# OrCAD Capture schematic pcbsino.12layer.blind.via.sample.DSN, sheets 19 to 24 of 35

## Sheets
19 Pg05: Power Supply 1: size C
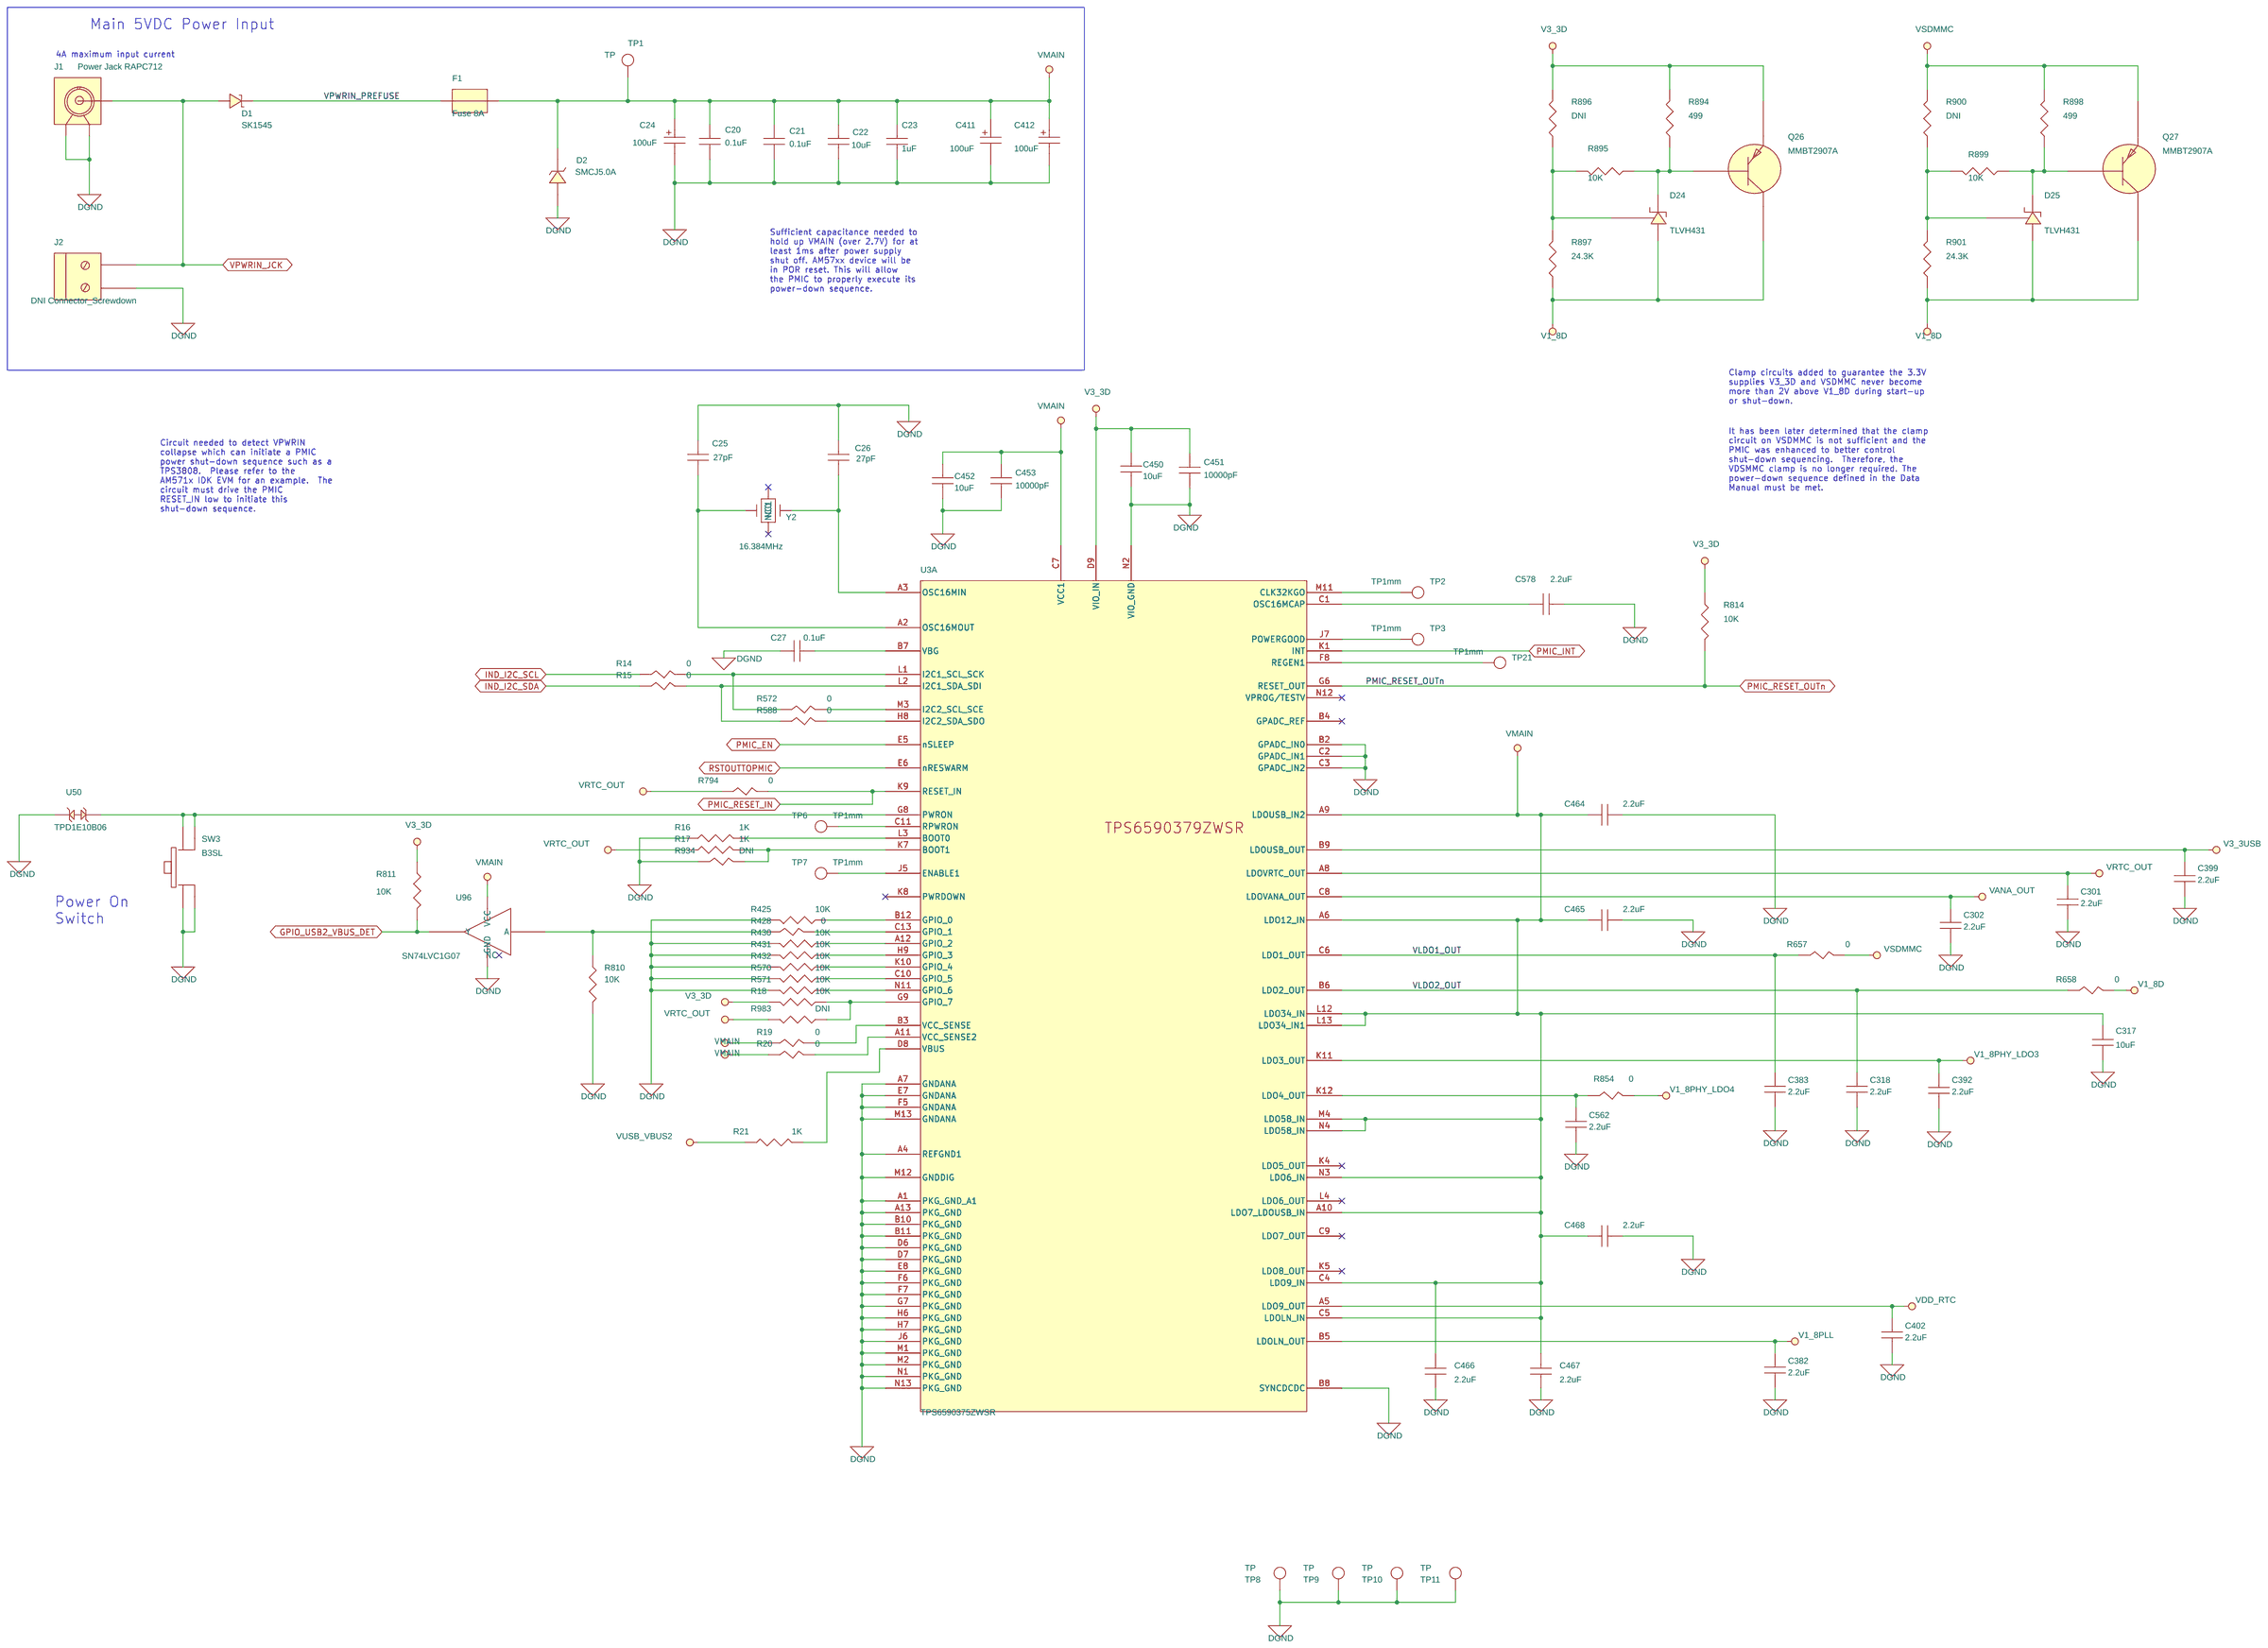
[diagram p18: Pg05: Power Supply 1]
20 Pg09: DDR3 Memory 2: size C
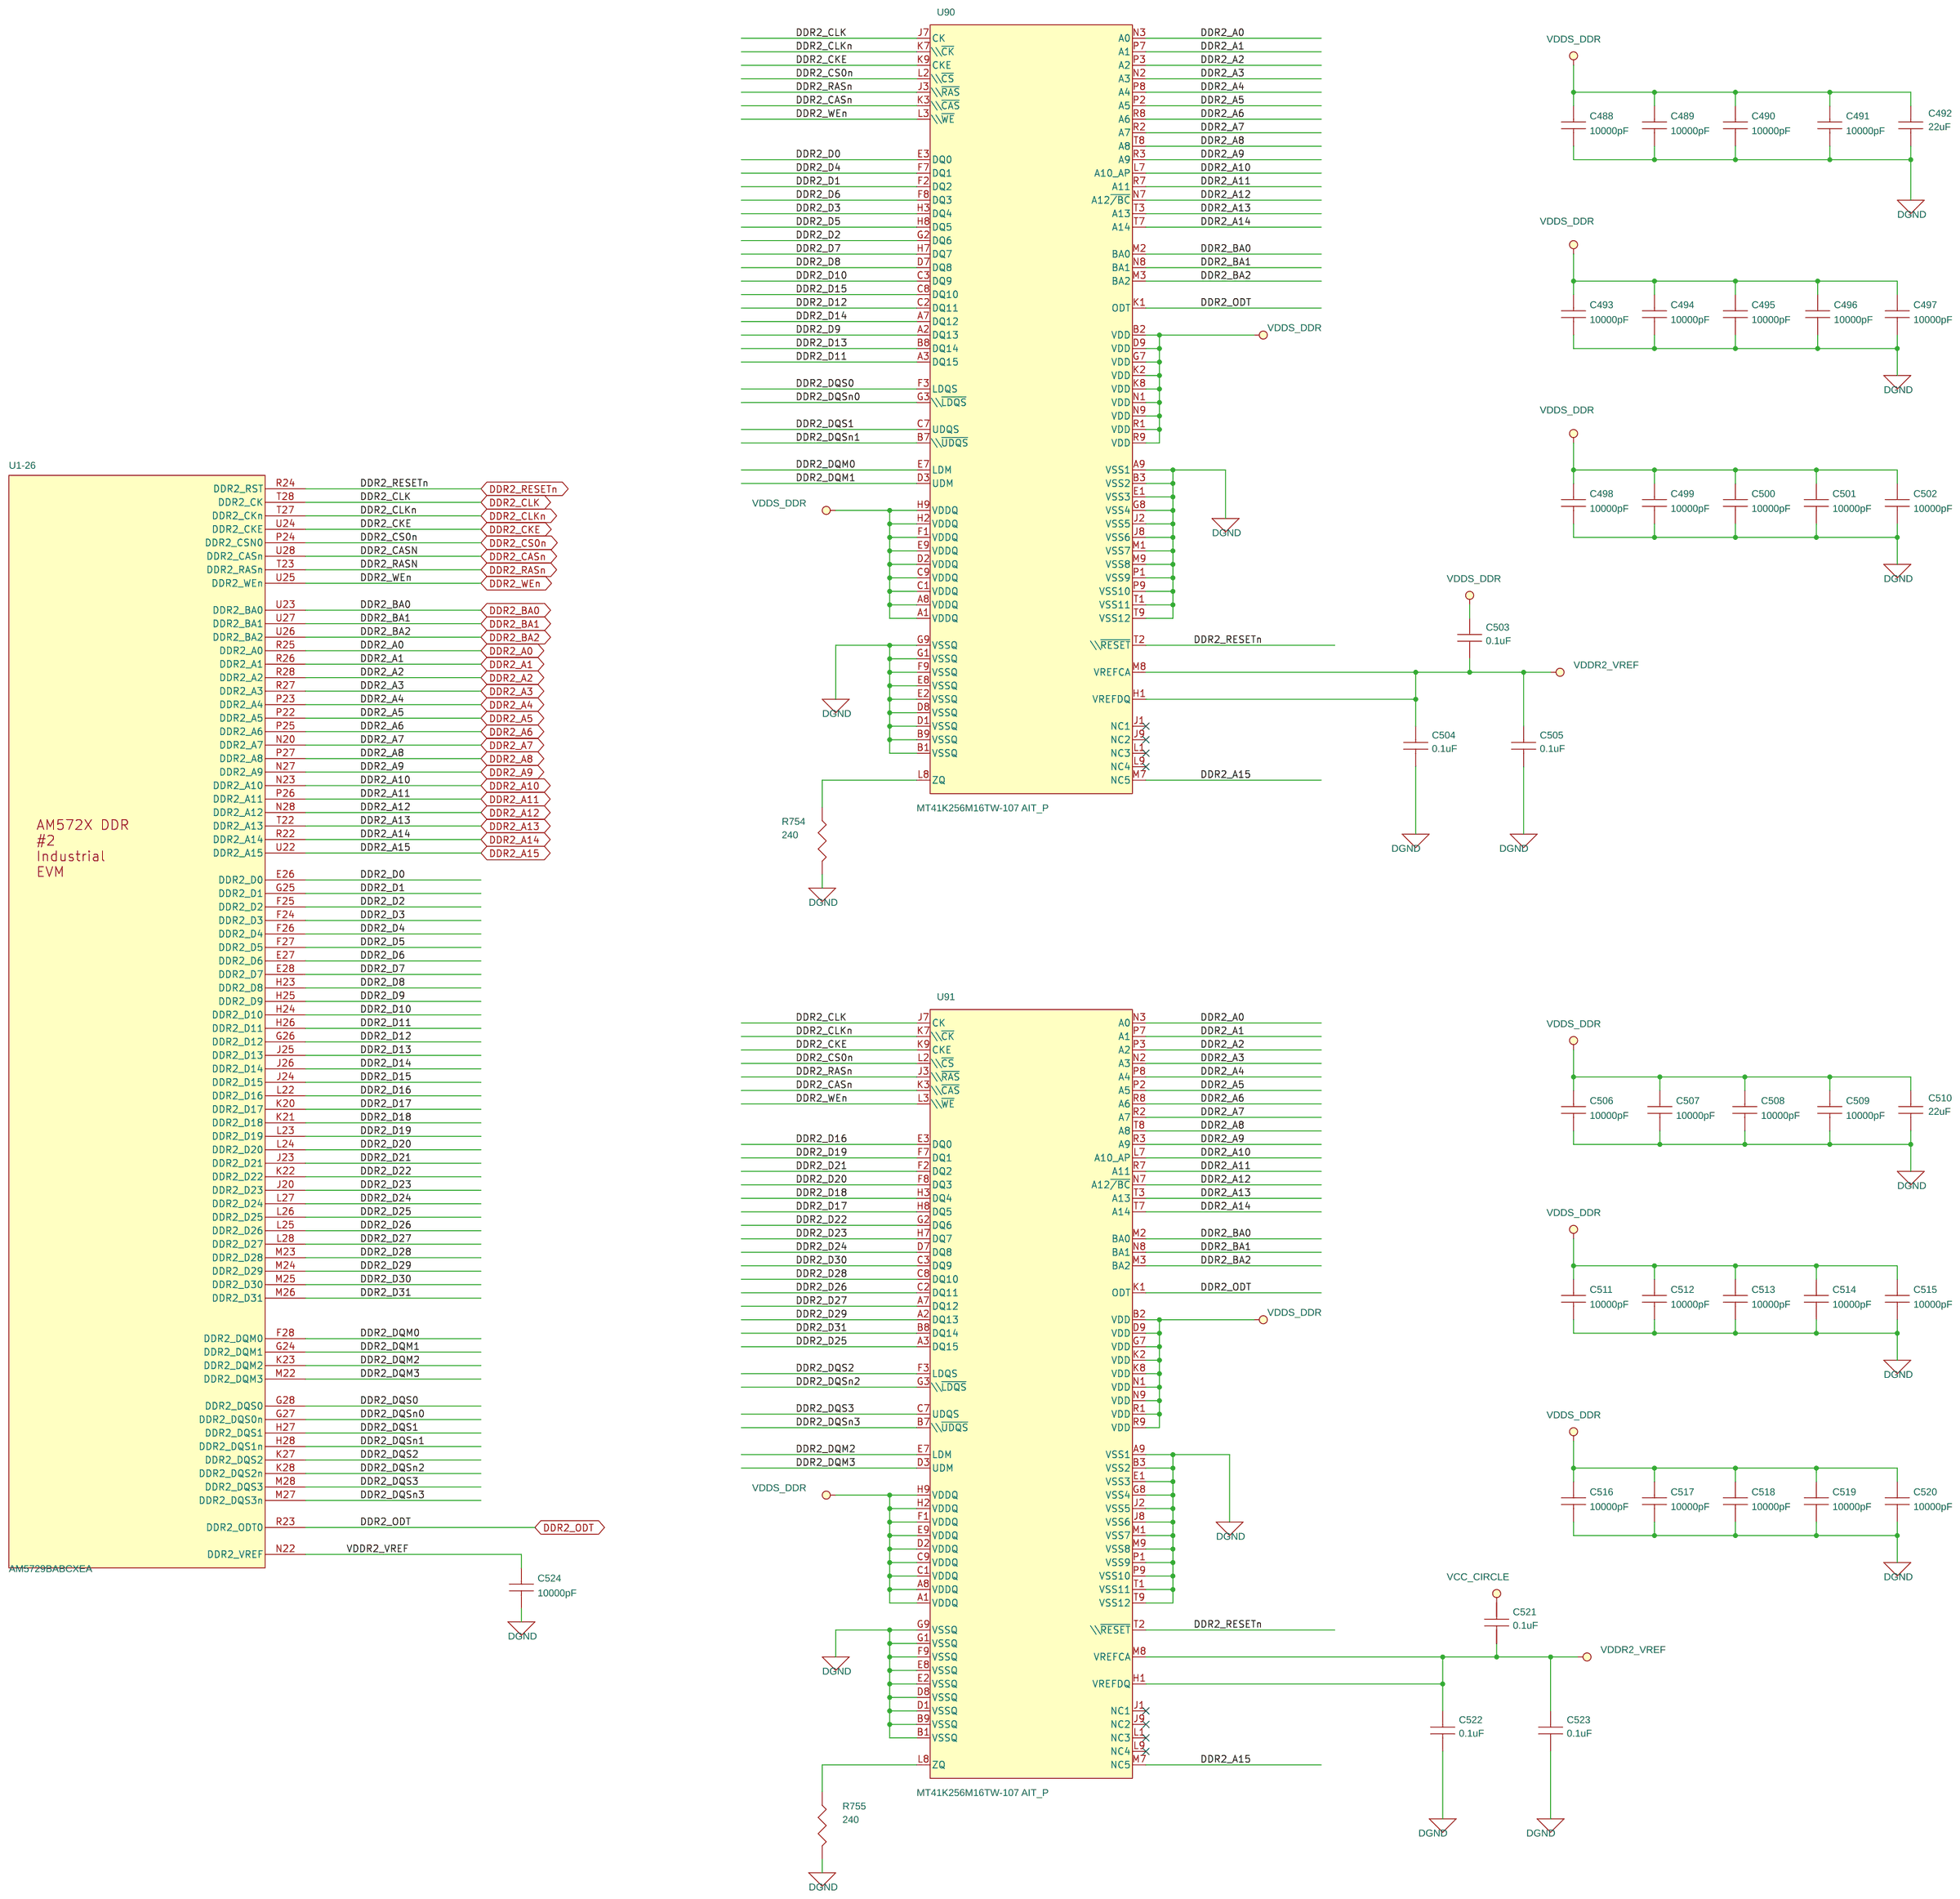
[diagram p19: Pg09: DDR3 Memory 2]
21 Pg06: Power Supply 2: size C
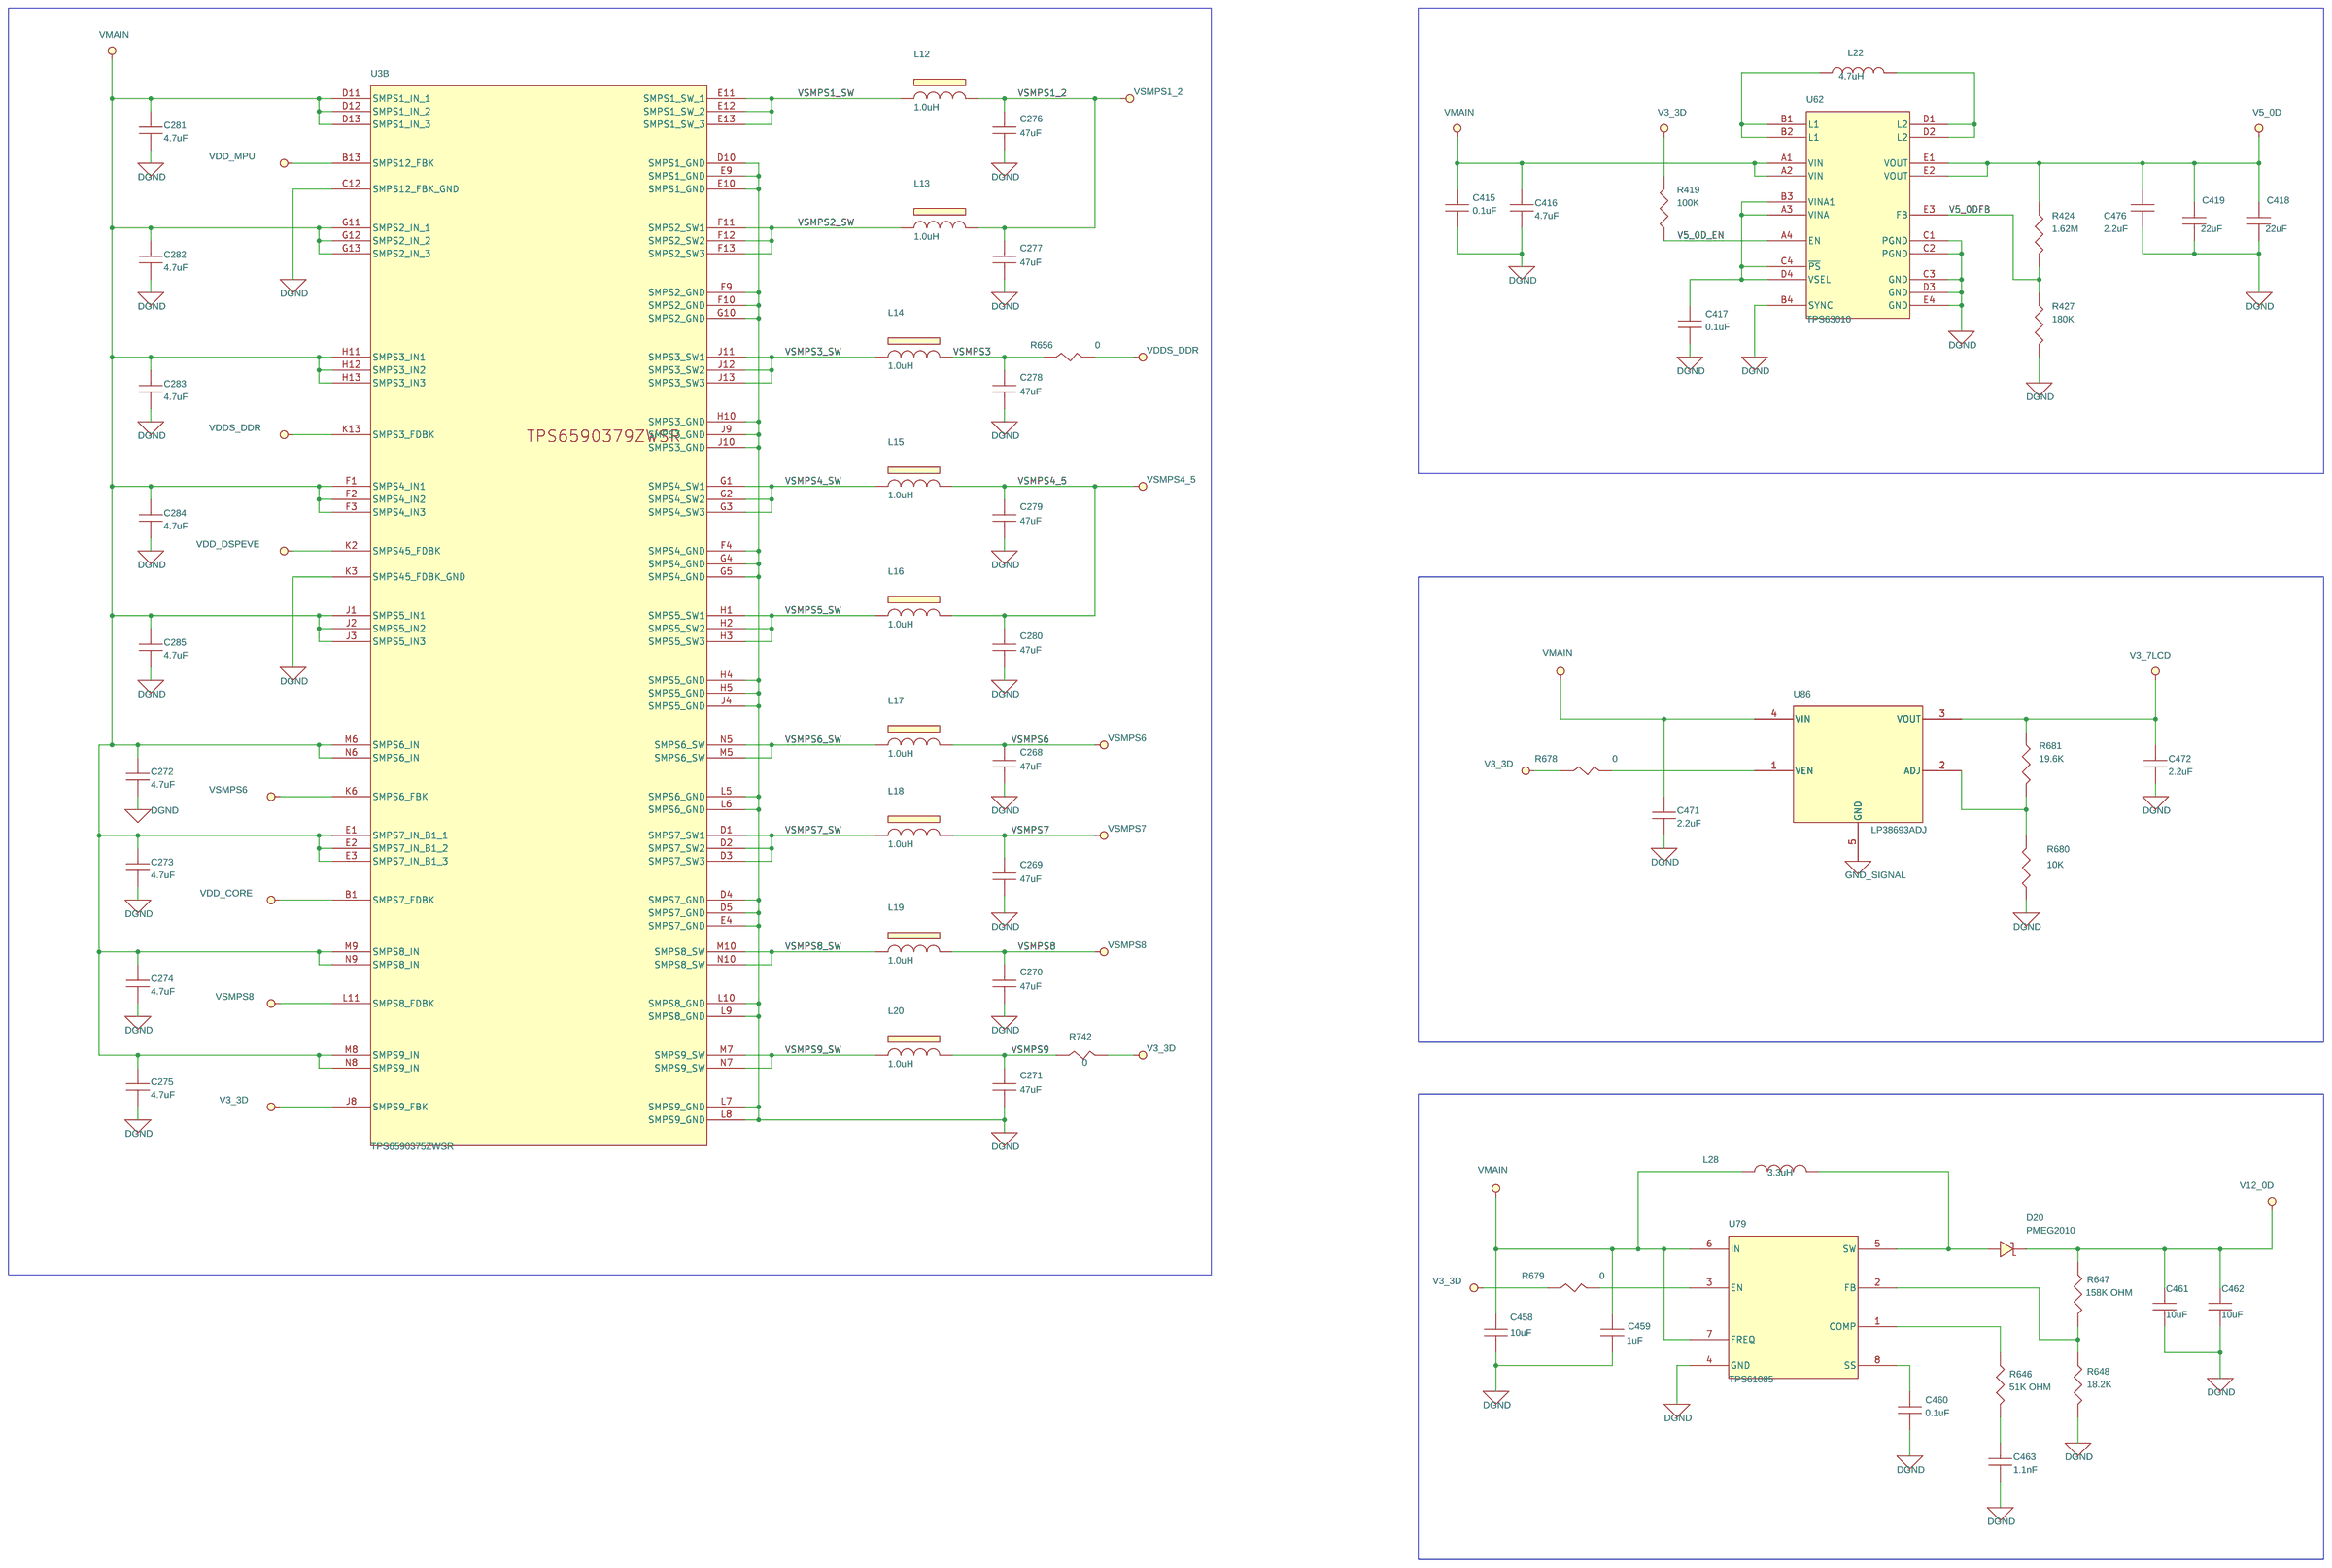
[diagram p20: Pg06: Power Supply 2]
22 Pg03: Processor Power: size C
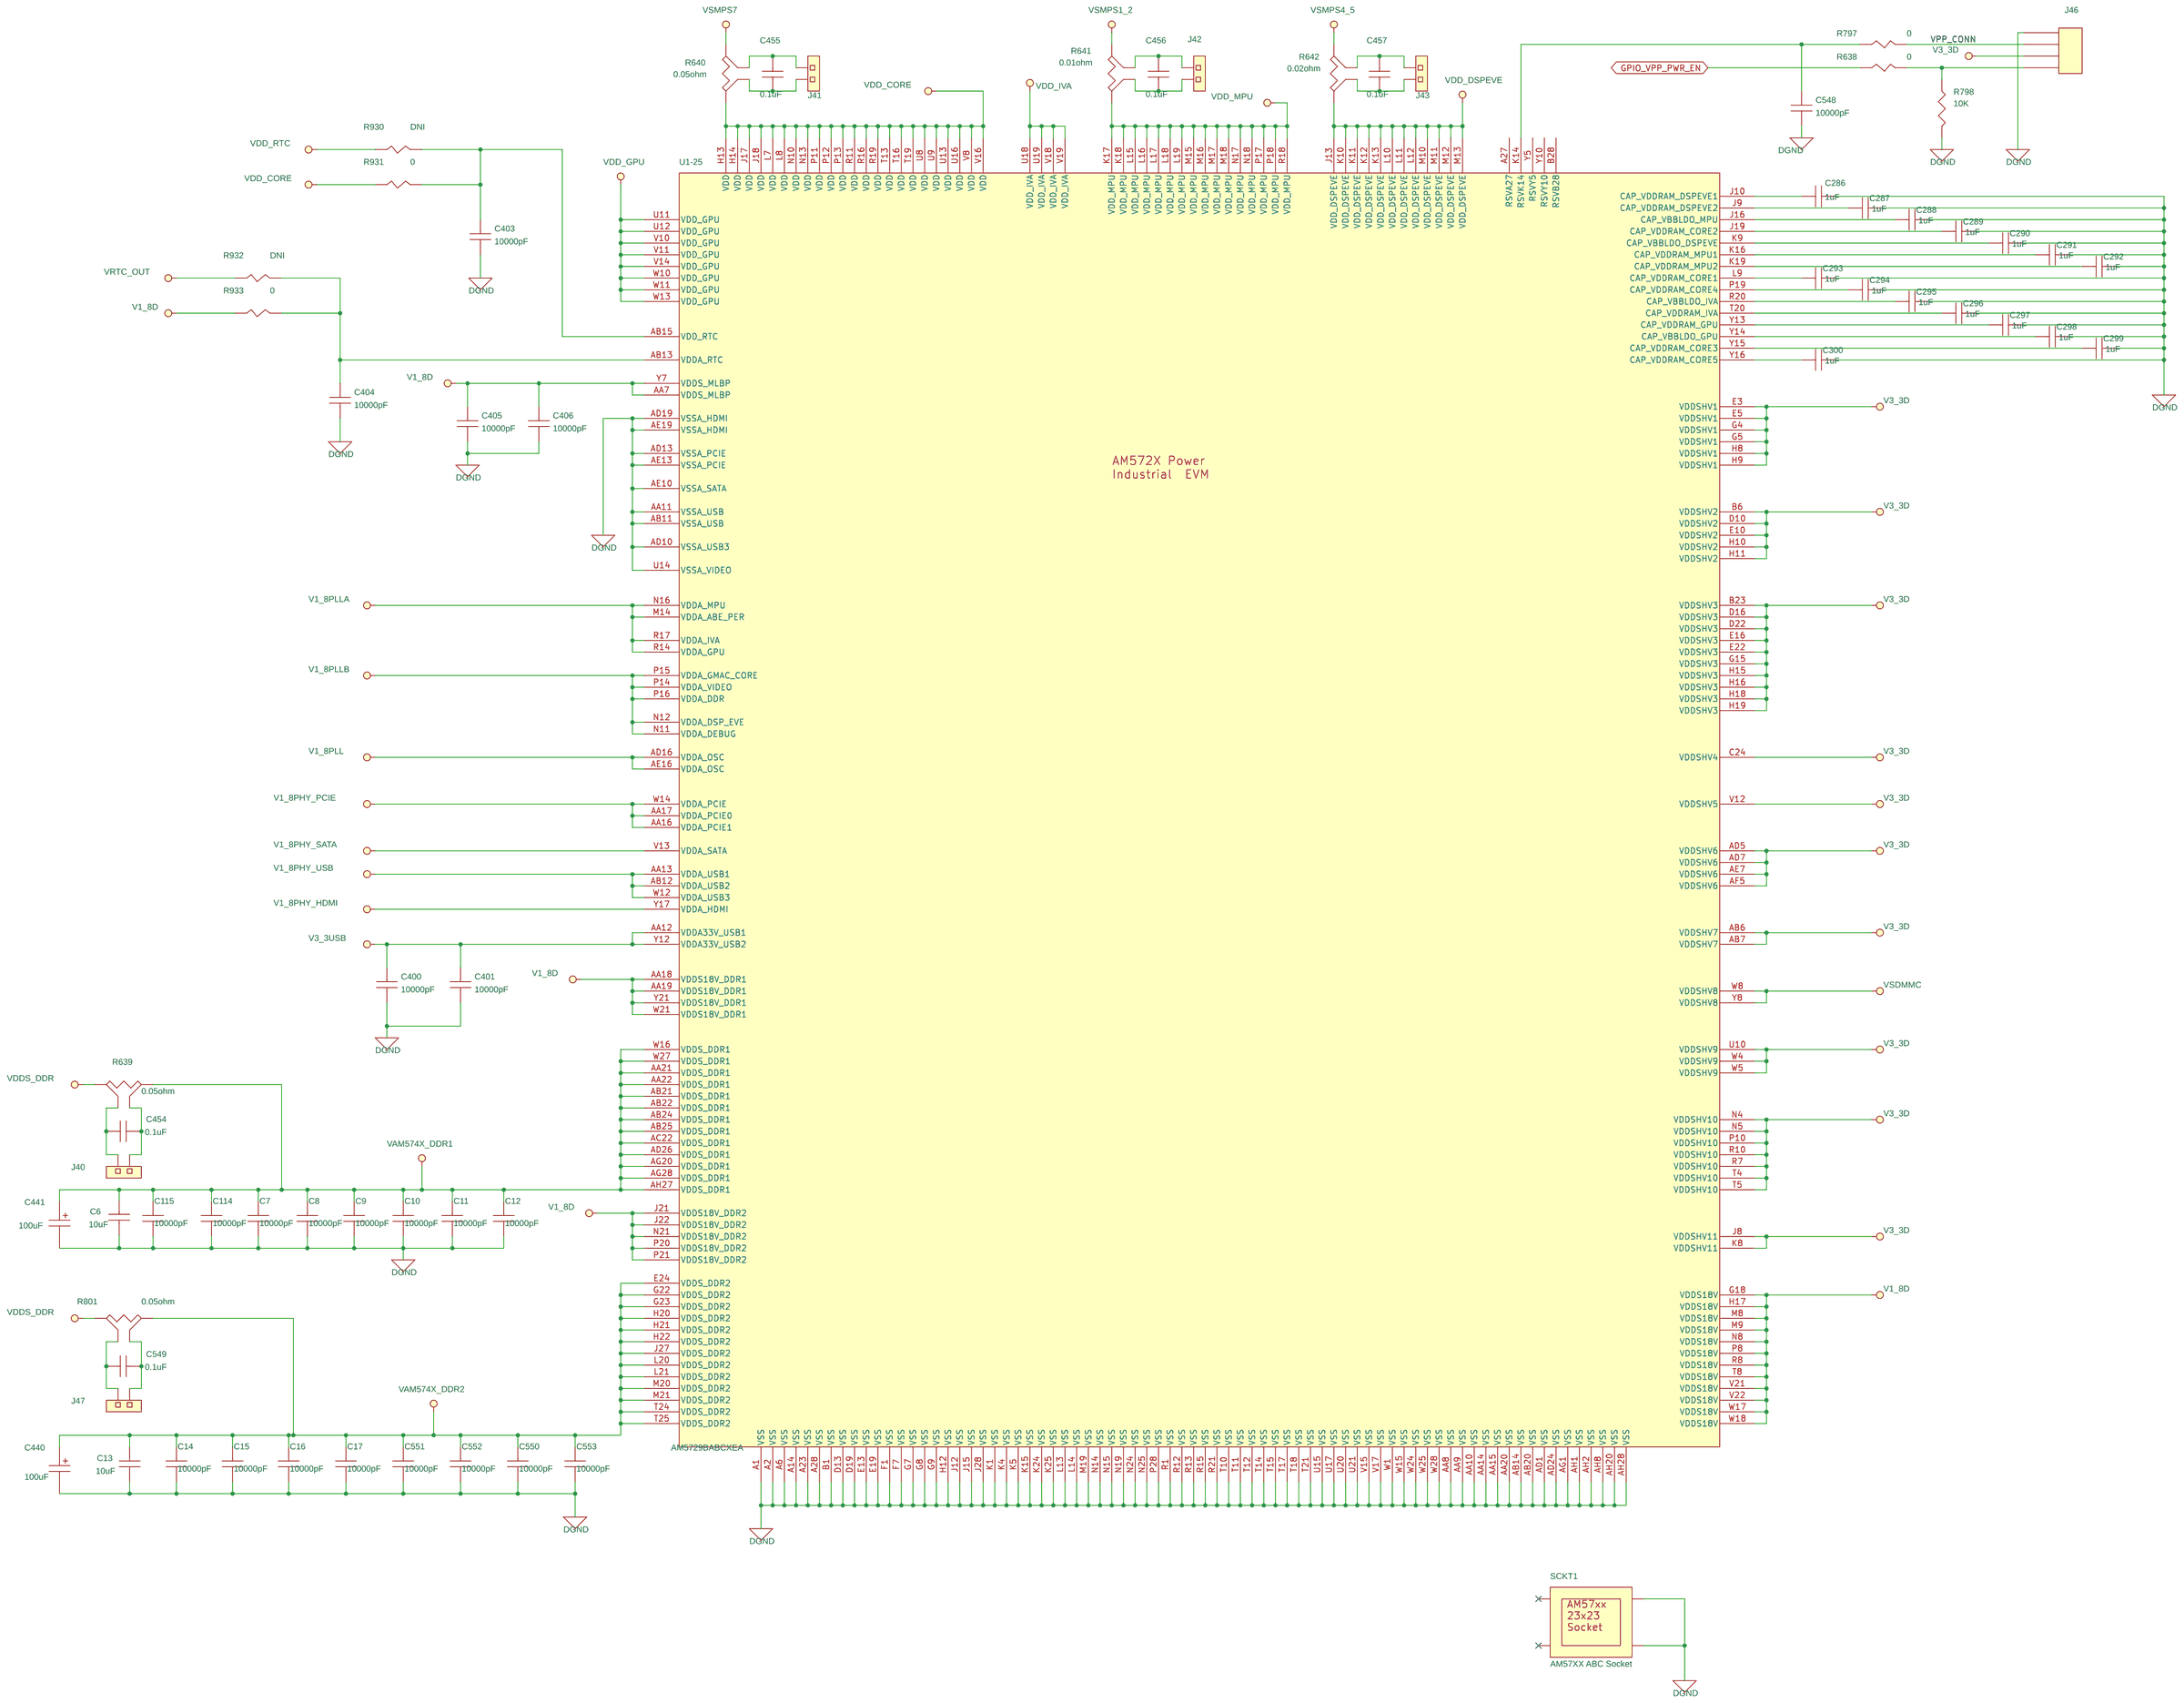
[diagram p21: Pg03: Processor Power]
23 Pg31: PCIE Connector: size C
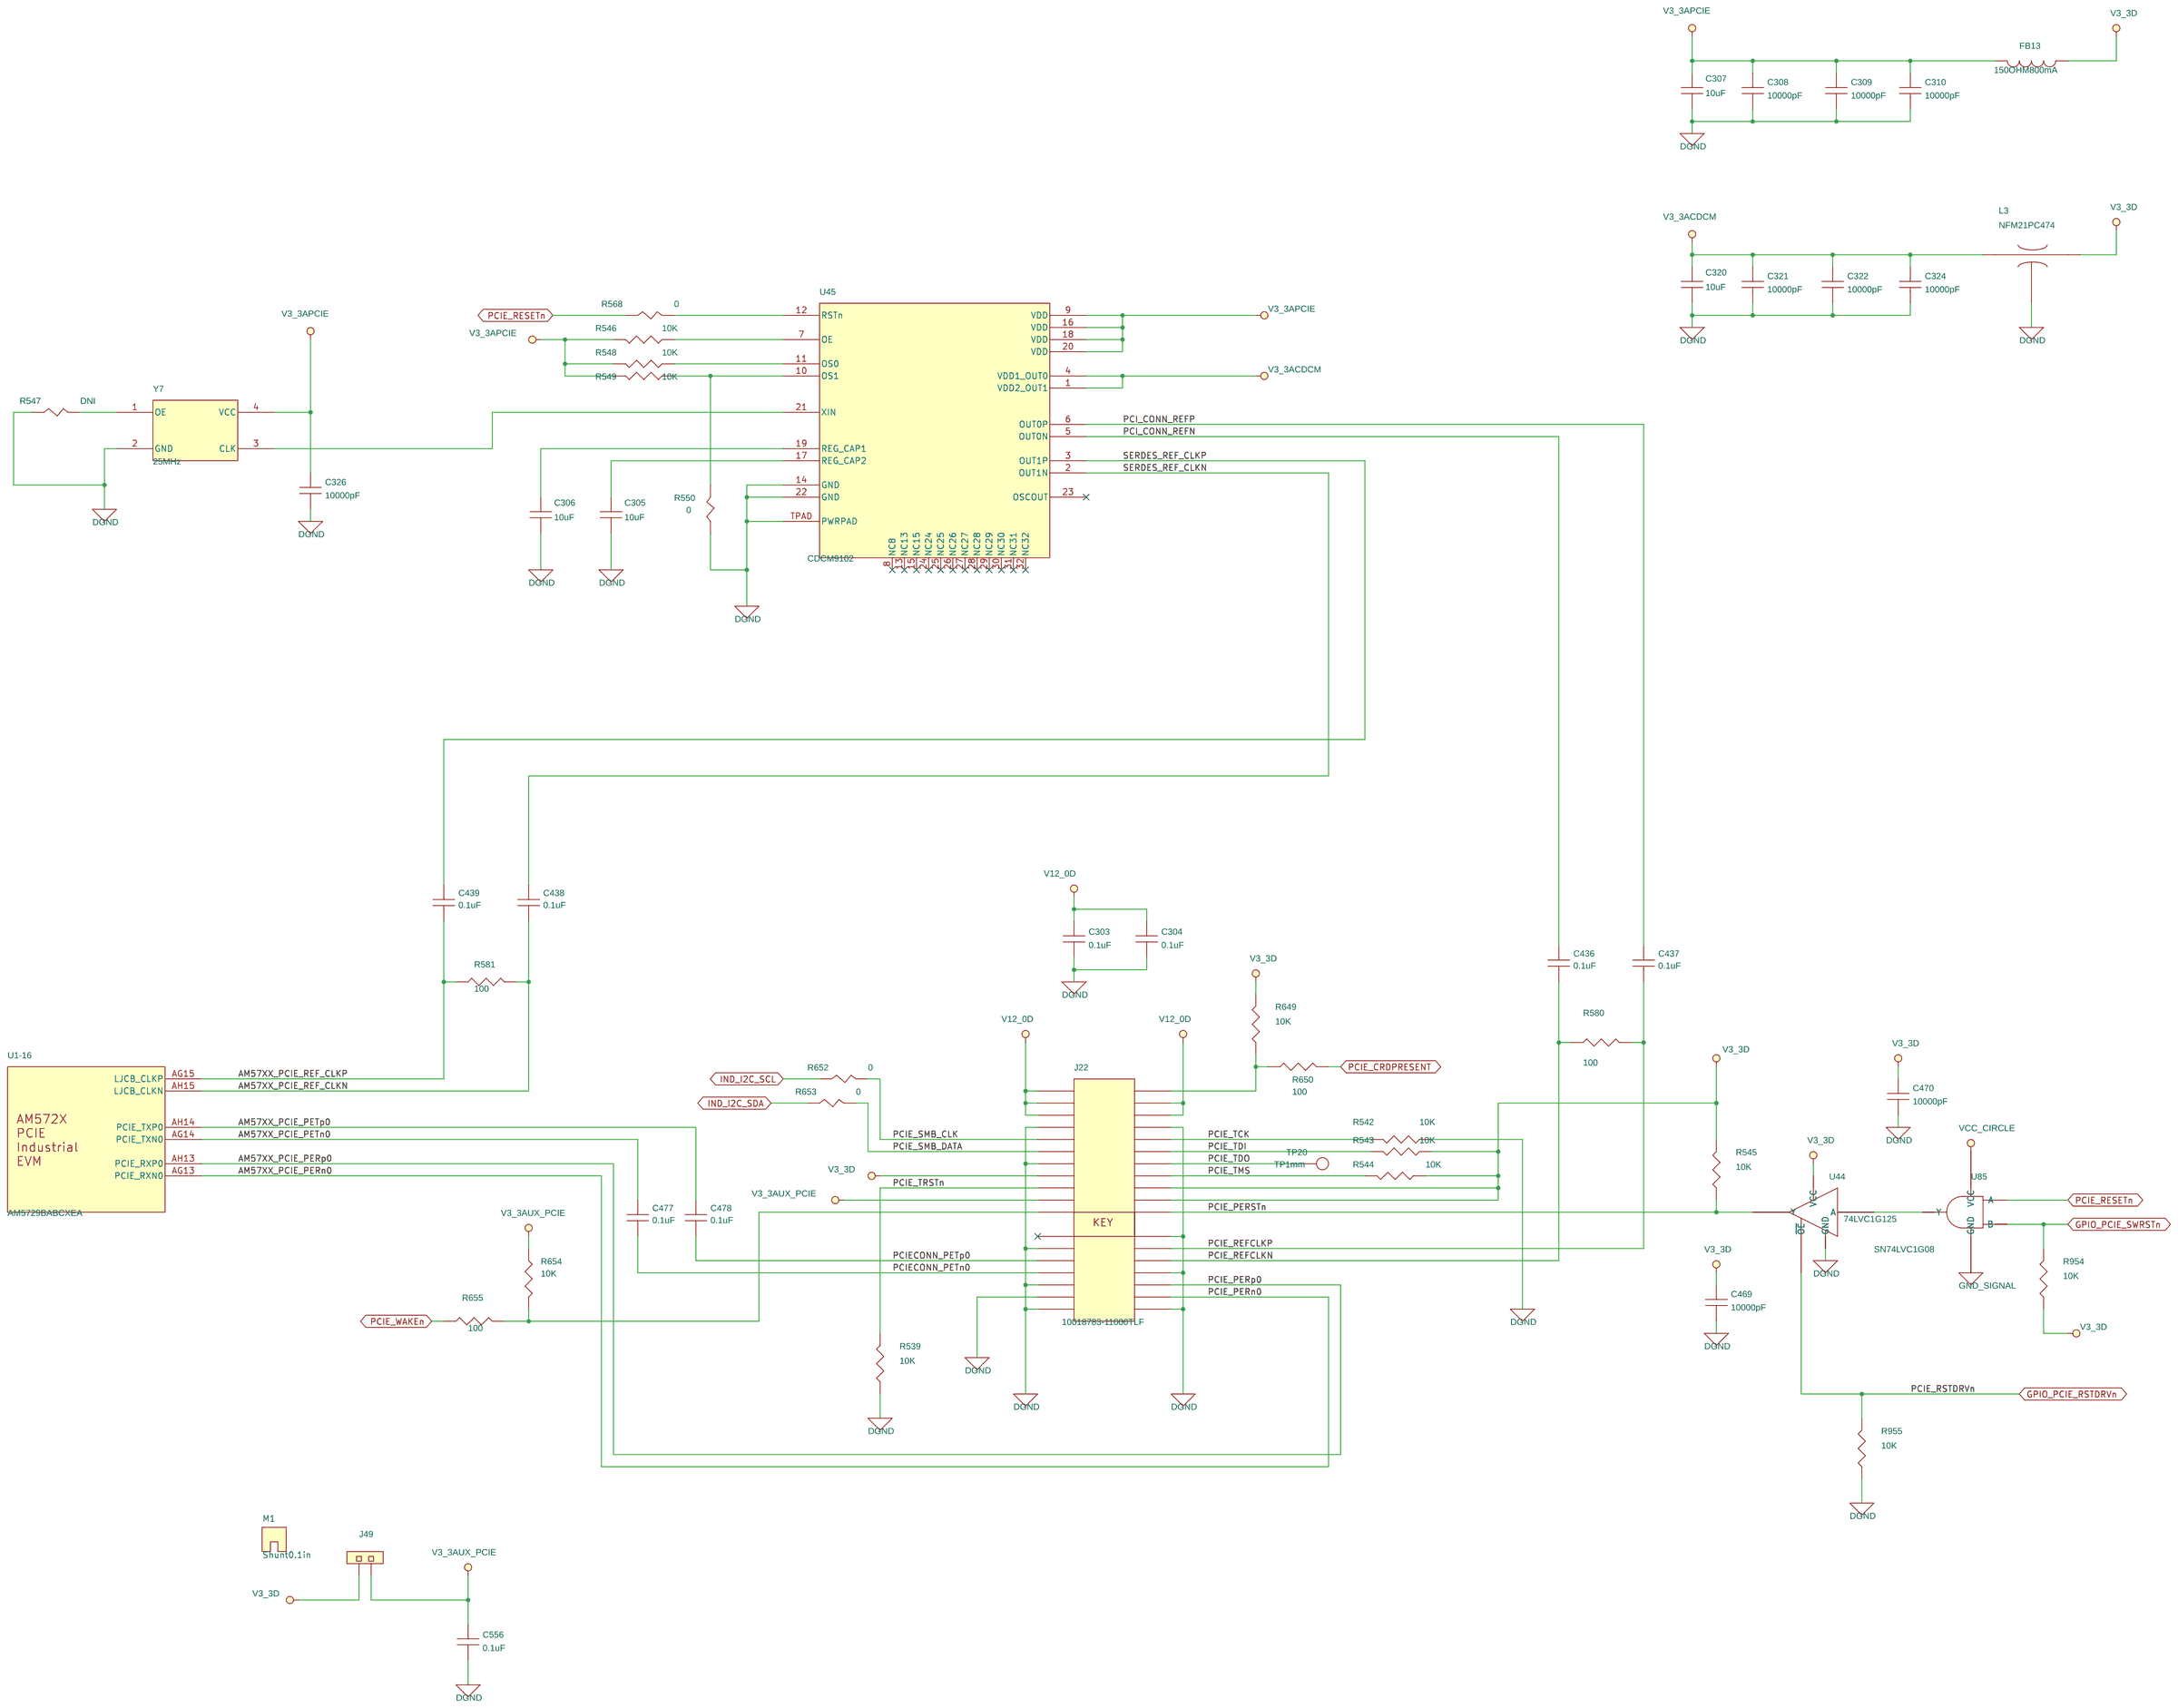
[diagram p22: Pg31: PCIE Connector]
24 Pg11: ICSS1 Ethernet 0: size C
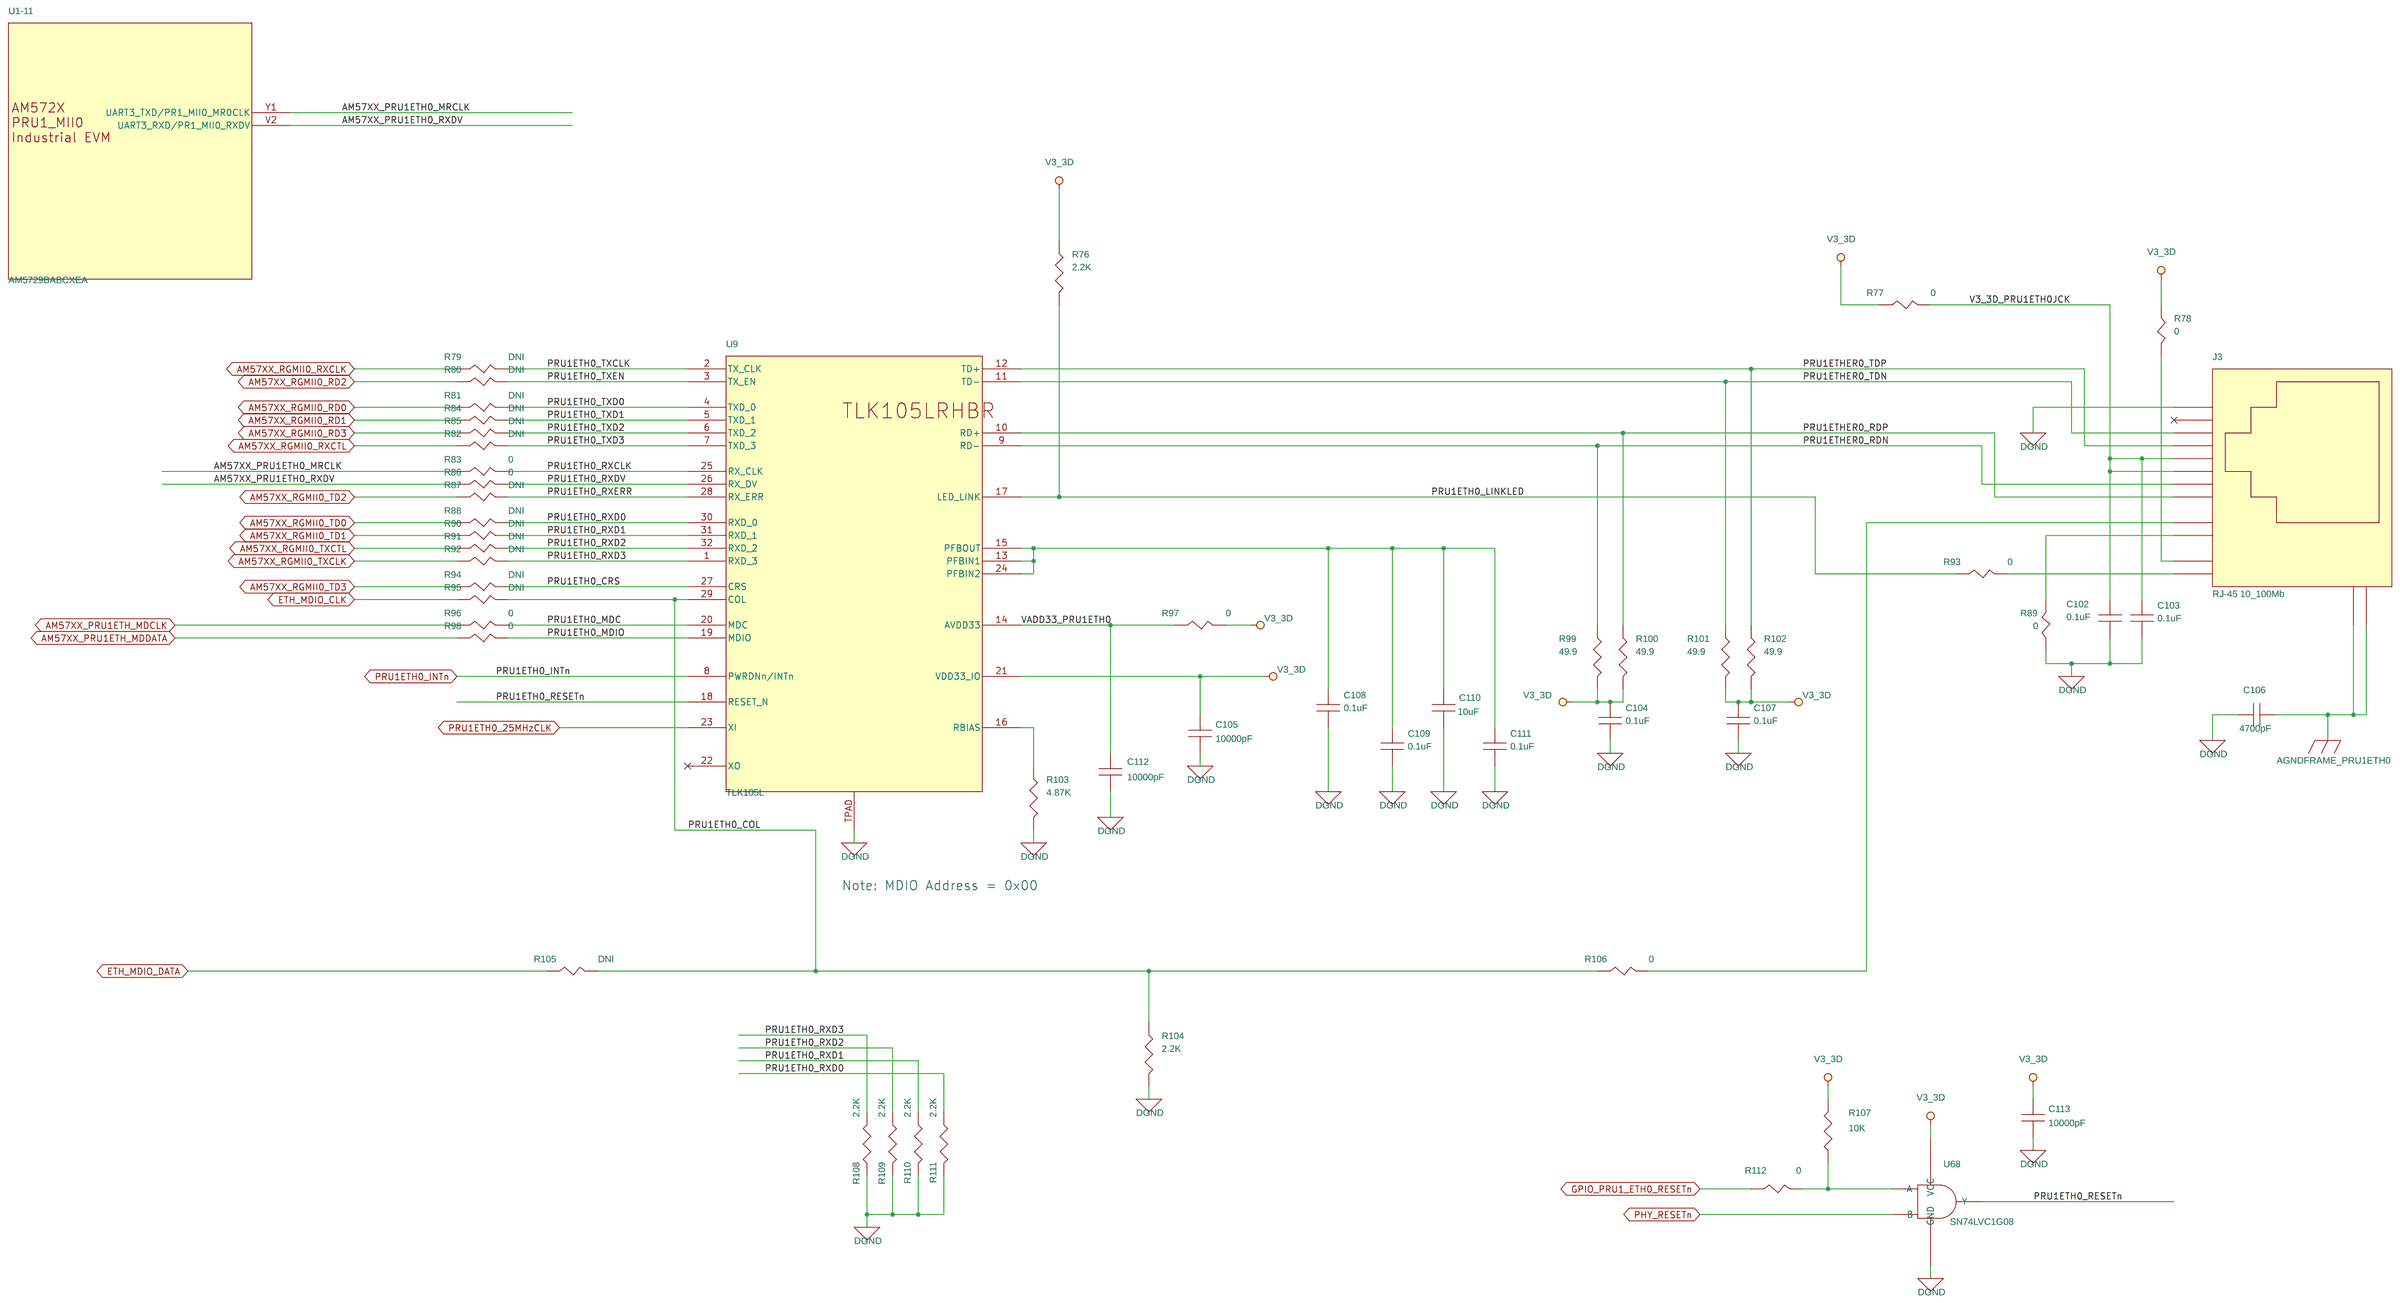
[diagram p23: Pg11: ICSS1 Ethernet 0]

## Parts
sheet Pg03: Processor Power
C6  10uF  [CC0805]
C7  10000pF  [CC0402]
C8  10000pF  [CC0402]
C9  10000pF  [CC0402]
C10  10000pF  [CC0402]
C11  10000pF  [CC0402]
C12  10000pF  [CC0402]
C13  10uF  [CC0805]
C14  10000pF  [CC0402]
C15  10000pF  [CC0402]
C16  10000pF  [CC0402]
C17  10000pF  [CC0402]
C114  10000pF  [CC0402]
C115  10000pF  [CC0402]
C286  1uF  [CC0402]
C287  1uF  [CC0402]
C288  1uF  [CC0402]
C289  1uF  [CC0402]
C290  1uF  [CC0402]
C291  1uF  [CC0402]
C292  1uF  [CC0402]
C293  1uF  [CC0402]
C294  1uF  [CC0402]
C295  1uF  [CC0402]
C296  1uF  [CC0402]
C297  1uF  [CC0402]
C298  1uF  [CC0402]
C299  1uF  [CC0402]
C300  1uF  [CC0402]
C400  10000pF  [CC0402]
C401  10000pF  [CC0402]
C403  10000pF  [CC0402]
C404  10000pF  [CC0402]
C405  10000pF  [CC0402]
C406  10000pF  [CC0402]
C440  100uF  [SM-7351-CAP-smdcan]
C441  100uF  [SM-7351-CAP-smdcan]
C454  0.1uF  [CC0402]
C455  0.1uF  [CC0402]
C456  0.1uF  [CC0402]
C457  0.1uF  [CC0402]
C548  10000pF  [CC0402]
C549  0.1uF  [CC0402]
C550  10000pF  [CC0402]
C551  10000pF  [CC0402]
C552  10000pF  [CC0402]
C553  10000pF  [CC0402]
J40  HEADER 2  [header_2x1]
J41  HEADER 2  [header_2x1]
J42  HEADER 2  [header_2x1]
J43  HEADER 2  [header_2x1]
J46  HEADER 4  [HDR1x4-330M]
J47  HEADER 2  [header_2x1]
R638  0  [SM-7351-RES-0402]
R639  0.05ohm  [SM_RES_LVK12]
R640  0.05ohm  [SM_RES_LVK12]
R641  0.01ohm  [SM_RES_LVK12]
R642  0.02ohm  [SM_RES_LVK12]
R797  0  [SM-7351-RES-0402]
R798  10K  [SM-7351-RES-0402]
R801  0.05ohm  [SM_RES_LVK12]
R930  DNI  [SM-7351-RES-0402]
R931  0  [SM-7351-RES-0402]
R932  DNI  [SM-7351-RES-0402]
R933  0  [SM-7351-RES-0402]
SCKT1  AM57XX ABC Socket  [SCK-SG-BGA-6334]
sheet Pg05: Power Supply 1
C20  0.1uF  [CC0402]
C21  0.1uF  [CC0402]
C22  10uF  [CC0805]
C23  1uF  [CC0603]
C24  100uF  [SM-7351-CAP-smdcan]
C25  27pF  [SM-7351-CAP-0402]
C26  27pF  [SM-7351-CAP-0402]
C27  0.1uF  [CC0402]
C301  2.2uF  [CC0402]
C302  2.2uF  [CC0402]
C317  10uF  [CC0805]
C318  2.2uF  [CC0402]
C382  2.2uF  [CC0402]
C383  2.2uF  [CC0402]
C392  2.2uF  [CC0402]
C399  2.2uF  [CC0402]
C402  2.2uF  [CC0402]
C411  100uF  [SM-7351-CAP-smdcan]
C412  100uF  [SM-7351-CAP-smdcan]
C450  10uF  [SM-7351-CAP-0603]
C451  10000pF  [CC0402]
C452  10uF  [SM-7351-CAP-0603]
C453  10000pF  [CC0402]
C464  2.2uF  [SM-7351-CAP-0805]
C465  2.2uF  [SM-7351-CAP-0805]
C466  2.2uF  [SM-7351-CAP-0805]
C467  2.2uF  [SM-7351-CAP-0805]
C468  2.2uF  [SM-7351-CAP-0805]
C562  2.2uF  [CC0402]
C578  2.2uF  [SM-7351-CAP-0805]
D1  SK1545  [sk1545]
D2  SMCJ5.0A  [SMCJ26CA]
D24  TLVH431  [sot23-3-44m]
D25  TLVH431  [sot23-3-44m]
F1  Fuse 8A  [fuse-0154]
J1  Power Jack RAPC712  [RAPC712]
J2  DNI Connector_Screwdown  [conn_osttc02]
Q26  MMBT2907A  [sot23-3-44m]
Q27  MMBT2907A  [sot23-3-44m]
R14  0  [SM-7351-RES-0402]
R15  0  [SM-7351-RES-0402]
R16  1K  [SM-7351-RES-0402]
R17  1K  [SM-7351-RES-0402]
R18  10K  [SM-7351-RES-0402]
R19  0  [SM-7351-RES-0402]
R20  0  [SM-7351-RES-0402]
R21  1K  [SM-7351-RES-0402]
R425  10K  [SM-7351-RES-0402]
R428  0  [SM-7351-RES-0402]
R430  10K  [SM-7351-RES-0402]
R431  10K  [SM-7351-RES-0402]
R432  10K  [SM-7351-RES-0402]
R570  10K  [SM-7351-RES-0402]
R571  10K  [SM-7351-RES-0402]
R572  0  [SM-7351-RES-0402]
R588  0  [SM-7351-RES-0402]
R657  0  [SM-7351-RES-0402]
R658  0  [SM-7351-RES-0402]
R794  0  [SM-7351-RES-0402]
R810  10K  [SM-7351-RES-0402]
R811  10K  [SM-7351-RES-0402]
R814  10K  [SM-7351-RES-0402]
R854  0  [SM-7351-RES-0402]
R894  499  [SM-7351-RES-0402]
R895  10K  [SM-7351-RES-0402]
R896  DNI  [SM-7351-RES-0402]
R897  24.3K  [SM-7351-RES-0402]
R898  499  [SM-7351-RES-0402]
R899  10K  [SM-7351-RES-0402]
R900  DNI  [SM-7351-RES-0402]
R901  24.3K  [SM-7351-RES-0402]
R934  DNI  [SM-7351-RES-0402]
R983  DNI  [SM-7351-RES-0402]
SW3  B3SL  [SW_B3SL-1022P]
TP1  TP  [TH_TP_5002]
TP2  TP1mm  [tp_smd1mmcircle]
TP3  TP1mm  [tp_smd1mmcircle]
TP6  TP1mm  [tp_smd1mmcircle]
TP7  TP1mm  [tp_smd1mmcircle]
TP8  TP  [TH_TP_5002]
TP9  TP  [TH_TP_5002]
TP10  TP  [TH_TP_5002]
TP11  TP  [TH_TP_5002]
TP21  TP1mm  [tp_smd1mmcircle]
U3  TPS6590375ZWSR  [bga12x12-169-55m]  (sections A,B)
U50  TPD1E10B06  [tpd1e10b06-2l]
U96  SN74LVC1G07  [SC70-5-43M]
Y2  16.384MHz  [xtal3225-39m]
sheet Pg06: Power Supply 2
C268  47uF  [CC1206]
C269  47uF  [CC1206]
C270  47uF  [CC1206]
C271  47uF  [CC1206]
C272  4.7uF  [SM-7351-CAP-0603]
C273  4.7uF  [SM-7351-CAP-0603]
C274  4.7uF  [SM-7351-CAP-0603]
C275  4.7uF  [SM-7351-CAP-0603]
C276  47uF  [CC1206]
C277  47uF  [CC1206]
C278  47uF  [CC1206]
C279  47uF  [CC1206]
C280  47uF  [CC1206]
C281  4.7uF  [SM-7351-CAP-0603]
C282  4.7uF  [SM-7351-CAP-0603]
C283  4.7uF  [SM-7351-CAP-0603]
C284  4.7uF  [SM-7351-CAP-0603]
C285  4.7uF  [SM-7351-CAP-0603]
C415  0.1uF  [CC0402]
C416  4.7uF  [SM-7351-CAP-0603]
C417  0.1uF  [CC0402]
C418  22uF  [CC0805]
C419  22uF  [CC0805]
C458  10uF  [CC0805]
C459  1uF  [CC0603]
C460  0.1uF  [CC0402]
C461  10uF  [CC0805]
C462  10uF  [CC0805]
C463  1.1nF  [SM-7351-CAP-0603]
C471  2.2uF  [SM-7351-CAP-0805]
C472  2.2uF  [SM-7351-CAP-0805]
C476  2.2uF  [SM-7351-CAP-0402]
D20  PMEG2010  [DFN1006D-2]
L12  1.0uH  [ind_ihlp1616ab]
L13  1.0uH  [ind_ihlp1616ab]
L14  1.0uH  [ind_ihlp1616ab]
L15  1.0uH  [ind_ihlp1616ab]
L16  1.0uH  [ind_ihlp1616ab]
L17  1.0uH  [ind_ihlp1616ab]
L18  1.0uH  [ind_ihlp1616ab]
L19  1.0uH  [ind_ihlp1616ab]
L20  1.0uH  [ind_ihlp1616ab]
L22  4.7uH  [IND_SRN5040]
L28  3.3uH  [vlcf5020t]
R419  100K  [SM-7351-RES-0402]
R424  1.62M  [SM-7351-RES-0402]
R427  180K  [SM-7351-RES-0402]
R646  51K OHM  [RC0402]
R647  158K OHM  [RC0402]
R648  18.2K  [SM-7351-RES-0402]
R656  0  [SM-7351-RES-0603]
R678  0  [SM-7351-RES-0402]
R679  0  [SM-7351-RES-0402]
R680  10K  [SM-7351-RES-0402]
R681  19.6K  [SM-7351-RES-0402]
R742  0  [SM-7351-RES-0603]
U62  TPS63010  [u_20_dsbga]
U79  TPS61085  [MSOP3X3-8-43M]
U86  LP38693ADJ  [SOT-223-5]
sheet Pg09: DDR3 Memory 2
C488  10000pF  [CC0402]
C489  10000pF  [CC0402]
C490  10000pF  [CC0402]
C491  10000pF  [CC0402]
C492  22uF  [CC0805]
C493  10000pF  [CC0402]
C494  10000pF  [CC0402]
C495  10000pF  [CC0402]
C496  10000pF  [CC0402]
C497  10000pF  [CC0402]
C498  10000pF  [CC0402]
C499  10000pF  [CC0402]
C500  10000pF  [CC0402]
C501  10000pF  [CC0402]
C502  10000pF  [CC0402]
C503  0.1uF  [CC0402]
C504  0.1uF  [CC0402]
C505  0.1uF  [CC0402]
C506  10000pF  [CC0402]
C507  10000pF  [CC0402]
C508  10000pF  [CC0402]
C509  10000pF  [CC0402]
C510  22uF  [CC0805]
C511  10000pF  [CC0402]
C512  10000pF  [CC0402]
C513  10000pF  [CC0402]
C514  10000pF  [CC0402]
C515  10000pF  [CC0402]
C516  10000pF  [CC0402]
C517  10000pF  [CC0402]
C518  10000pF  [CC0402]
C519  10000pF  [CC0402]
C520  10000pF  [CC0402]
C521  0.1uF  [CC0402]
C522  0.1uF  [CC0402]
C523  0.1uF  [CC0402]
C524  10000pF  [CC0402]
R754  240  [sm-7351-res-0402]
R755  240  [sm-7351-res-0402]
U90  MT41K256M16TW-107 AIT_P  [BGA96C80P9X16_800X1400X120]
U91  MT41K256M16TW-107 AIT_P  [BGA96C80P9X16_800X1400X120]
sheet Pg11: ICSS1 Ethernet 0
C102  0.1uF  [CC0402]
C103  0.1uF  [CC0402]
C104  0.1uF  [CC0402]
C105  10000pF  [CC0402]
C106  4700pF  [CC0402]
C107  0.1uF  [CC0402]
C108  0.1uF  [CC0402]
C109  0.1uF  [CC0402]
C110  10uF  [CC0805]
C111  0.1uF  [CC0402]
C112  10000pF  [CC0402]
C113  10000pF  [CC0402]
J3  RJ-45 10_100Mb  [CNRJ45-1X1WLED]
R76  2.2K  [sm-7351-res-0402]
R77  0  [SM-7351-RES-0402]
R78  0  [SM-7351-RES-0402]
R79  DNI  [SM-7351-RES-0402]
R80  DNI  [SM-7351-RES-0402]
R81  DNI  [SM-7351-RES-0402]
R82  DNI  [SM-7351-RES-0402]
R83  0  [SM-7351-RES-0402]
R84  DNI  [SM-7351-RES-0402]
R85  DNI  [SM-7351-RES-0402]
R86  0  [SM-7351-RES-0402]
R87  DNI  [SM-7351-RES-0402]
R88  DNI  [SM-7351-RES-0402]
R89  0  [SM-7351-RES-0402]
R90  DNI  [SM-7351-RES-0402]
R91  DNI  [SM-7351-RES-0402]
R92  DNI  [SM-7351-RES-0402]
R93  0  [SM-7351-RES-0402]
R94  DNI  [SM-7351-RES-0402]
R95  DNI  [SM-7351-RES-0402]
R96  0  [SM-7351-RES-0402]
R97  0  [SM-7351-RES-0603]
R98  0  [SM-7351-RES-0402]
R99  49.9  [SM-7351-RES-0402]
R100  49.9  [SM-7351-RES-0402]
R101  49.9  [SM-7351-RES-0402]
R102  49.9  [SM-7351-RES-0402]
R103  4.87K  [SM-7351-RES-0402]
R104  2.2K  [sm-7351-res-0402]
R105  DNI  [SM-7351-RES-0402]
R106  0  [SM-7351-RES-0402]
R107  10K  [SM-7351-RES-0402]
R108  2.2K  [sm-7351-res-0402]
R109  2.2K  [sm-7351-res-0402]
R110  2.2K  [sm-7351-res-0402]
R111  2.2K  [sm-7351-res-0402]
R112  0  [SM-7351-RES-0402]
U9  TLK105L  [qfn5x5-32-39m]
U68  SN74LVC1G08  [sm-so-sc70-5]
sheet Pg22: HDMI
U1  AM5729BABCXEA  [BGA23X23-760-117M]  (sections -1,-10,-11,-12,-13,-14,-15,-16,-17,-18,-19,-2,-20,-21,-22,-23,-24,-25,-26,-27,-28,-29,-3,-4,-5,-6,-7,-8,-9)
sheet Pg31: PCIE Connector
C303  0.1uF  [CC0402]
C304  0.1uF  [CC0402]
C305  10uF  [CC0805]
C306  10uF  [CC0805]
C307  10uF  [CC0805]
C308  10000pF  [CC0402]
C309  10000pF  [CC0402]
C310  10000pF  [CC0402]
C320  10uF  [CC0805]
C321  10000pF  [CC0402]
C322  10000pF  [CC0402]
C324  10000pF  [CC0402]
C326  10000pF  [CC0402]
C436  0.1uF  [CC0402]
C437  0.1uF  [CC0402]
C438  0.1uF  [CC0402]
C439  0.1uF  [CC0402]
C469  10000pF  [CC0402]
C470  10000pF  [CC0402]
C477  0.1uF  [CC0402]
C478  0.1uF  [CC0402]
C556  0.1uF  [CC0402]
FB13  150OHM800mA  [sm-7351-ind-0805]
J22  10018783-11000TLF  [CN_10018783-11000TLF]
J49  HEADER 2  [header_2x1]
L3  NFM21PC474  [FILT-NFM21PC]
M1  Shunt0.1in  [none]
R539  10K  [SM-7351-RES-0402]
R542  10K  [SM-7351-RES-0402]
R543  10K  [SM-7351-RES-0402]
R544  10K  [SM-7351-RES-0402]
R545  10K  [SM-7351-RES-0402]
R546  10K  [SM-7351-RES-0402]
R547  DNI  [SM-7351-RES-0402]
R548  10K  [SM-7351-RES-0402]
R549  10K  [SM-7351-RES-0402]
R550  0  [SM-7351-RES-0402]
R568  0  [SM-7351-RES-0402]
R580  100  [SM-7351-RES-0402]
R581  100  [SM-7351-RES-0402]
R649  10K  [SM-7351-RES-0402]
R650  100  [SM-7351-RES-0402]
R652  0  [SM-7351-RES-0402]
R653  0  [SM-7351-RES-0402]
R654  10K  [SM-7351-RES-0402]
R655  100  [SM-7351-RES-0402]
R954  10K  [SM-7351-RES-0402]
R955  10K  [SM-7351-RES-0402]
TP20  TP1mm  [tp_smd1mmcircle]
U44  74LVC1G125  [SC70-5-43M]
U45  CDCM9102  [qfn5x5-32ti-39m]
U85  SN74LVC1G08  [sm-so-sc70-5]
Y7  25MHz  [asf_smd3_2x5mm]

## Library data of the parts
C6 C13 C22 C110 C305-C307 C317 C320 C458 = CL21A106KOQNNNG
C7-C12 C14-C17 C105 C112-C115 C308-C310 C321 C322 C324 C326 C400 C401 C403-C406 C451 C453 C469 C470 C488-C491 C493-C502 C506-C509 C511-C520 C524 C548 C550-C553 = CC0402KRX7R7BB103
C286-C300 = CGB2A1X5R1E105K033BC
C24 C411 C412 C440 C441 = 1C_100uFCapacitor16V20%ElecPoly: Capacitor 100uF 16V Polymer 20% smd can; MANUFACTURER: United Chemicon
C20 C21 C102-C104 C107-C109 C111 C415 C417 C436-C439 C454-C457 C460 C477 C478 C503-C505 C521-C523 C549 = CC0402JRX7R7BB104
J40-J43 J47 J49 = 2H_Header_0: Single Line Header 2pin Tin 0.1in pitch; MANUFACTURER: OnShoreTechnology
J46 = 2H_Header_4x1: Single Line Header 4pin Tin; MANUFACTURER: Sullins
R14 R15 R19 R20 R77-R96 R98 R105 R106 R112 R428 R547 R550 R568 R572 R588 R638 R652 R653 R657 R658 R678 R679 R794 R797 R854 R930-R934 = 1R_ZeroOhmResistor1_16W0402: Resistor Zero ohm Jumper 0402; MANUFACTURER: PANASONIC
R639 R640 R801 = LVK12R050DER: Resistor 0.05ohm 0.5W Sense 0.5% 1206,smd-4pin; MANUFACTURER: Ohmite
R641 = LVK12R010DER: Resistor 0.05ohm 0.5W Sense 0.5% 1206,smd-4pin; MANUFACTURER: Ohmite
R642 = LVK12R020FER: Resistor 0.02ohm 0.5W Sense 1% 1206; MANUFACTURER: Ohmite
R18 R107 R425 R430-R432 R539 R542-R546 R548 R549 R570 R571 R649 R654 R798 R810 R811 R814 R895 R896 R899 R900 R954 R955 R983 = RMCF0402FT10K0
SCKT1 = AM57XX_SOCKET: Socket for AM57XX 23mmx23mm ZDN Package; DNI: DNI; MANUFACTURER: Ironwood
C23 C459 = CL10A105KB8NNNC
C25 C26 = C0402C270J5GACTU
C27 C303 C304 C556 = CGA2B3X7R1H104K050BE
C301 C302 C318 C382 C383 C392 C399 C402 C562 = C1005X5R0J225M050BC
C450 C452 = 1C_10uFCapacitor6.3V20%0603: Capacitor 10uF 6.3V 20% Ceramic X5R 0603; MANUFACTURER: Murata
C464-C468 C471 C472 C578 = 1C_2.2uF16V10%SMD0805: Capacitor 2.2uF 16V 10% 0805; MANUFACTURER: Kemet
D1 = 1E_Diode_15ARect_rev45V: Diode Power Rectifier 15A Schottky Rev 45V; MANUFACTURER: Micro Commercial Co; TIIntPartnumber: _1E0014
D2 = SMCJ5.0A
D24 D25 = TLVH431_0: Adjustable Precision Shunt Regulator; MANUFACTURER: TI; MfrNum: TLVH431CDBZT; PartName: Adjustable Precision Shunt Regulator
F1 = 1P_Fuse_0: Fuse Block with 8A Fuse; MANUFACTURER: Littelfuse
J1 = 2J_Conn_PwrJack_RAPC712: Jack Power Right Angle 2conductor 2.5mm center; MANUFACTURER: Switchcraft
J2 = 2C_Conn_LeadScrewDown_2pin: Connector 2pin screw down 15A 300VAC blue; MANUFACTURER: OnShore Technology
Q26 Q27 = 1Q_MOSFET_PChan_FDT434P_0: TRANS GP PNP 60V .6A; MANUFACTURER: ON SEMICONDUCTOR; MfrNum: MMBT2907AWT1G; PartName: TRANS GP PNP 60V .6A
R16 R17 R21 = 1R_1KOhmResistor1_16W0402: Resistor 1Kohm 1/16W 5% 0402; MANUFACTURER: PANASONIC
R894 R898 = RMCF0402FT499R
R897 R901 = RMCF0402FT24K3
SW3 = 2W_Switch_Pushbuttonsmd: Switch Push Button tactile NO; MANUFACTURER: Omron
TP1 TP8-TP11 = 2H_TestPointThroughHole: Testpoint Miniature Through Hole; MANUFACTURER: Keystone Electronics
TP2 TP3 TP6 TP7 TP20 TP21 = 2H_Testpoint_SMD1mmCircle: Testpoint SMD 1mm circle pad; MANUFACTURER: N/A
U3 = TPS6590379ZWSR: MANUFACTURER: TEXAS INSTRUMENTS
U50 = TPD1E10B06DPYR: TVS DIODE 5.5V 14V 2X1SON; MANUFACTURER: TI
U96 = SN74LVC1G07DCKRE4: MANUFACTURER: TEXAS INSTRUMENT
Y2 = 1Y_Crystal16.384MHz: Crystal 16.384MHz 30ppm/50ppm load cap 18pF; MANUFACTURER: Citizen
C268-C271 C276-C280 = CL31A476MPHNNNE
C272-C275 C281-C285 C416 = 1C_4.7uFCapacitor16V10%0603: Capacitor Ceramic 4.7uF 16V 10% 0603; MANUFACTURER: Taiyo Yuden
C418 C419 C492 C510 = CL21A226MOCLRNC
C461 C462 = GRM21BR6YA106KE43L
C463 = 1C_1.1nFCapacitor50V5%0603: Capacitor 1.1nF 50V 5% Ceramic 0603; MANUFACTURER: Murata
C476 = 1C_2.2uFCapacitor10V20%smd0402: Capacitor 2.2uF 10V 20% Ceramic 0402; MANUFACTURER: Taiyo Yuden
D20 = PMEG2010BELD,315: Diode Schottky 1A 20V Schottky; MANUFACTURER: NEXPERIA
L12-L20 = SRP4012TA-1R0M
L22 = SRN5040-4R7M
L28 = 1L_0.5Asmd: Inductor 3.3uH smt 1.5A; MANUFACTURER: Sumida
R419 = 1R_100KOhmResistor1_16W0402: Resistor 100Kohm 1/16W 1% 0402; MANUFACTURER: STACKPOLE ELECTRONICS
R424 = 1R_1.62MOhmResistor1_16W0402: Resistor 1.62Mohm 1/16W 1% 0402; MANUFACTURER: Vishay/Dale
R427 = 1R_180KOhmResistor1_16W0402: Resistor 180Kohm 1/16W 1% 0402; MANUFACTURER: STACKPOLE ELECTRONICS
R646 = RC0402FR-0751KL
R647 = RC0402FR-07158KL
R648 = 1R_18.2Kohm1_16W1%smd0402: Resistor 18.2Kohm 1/16W 1% 0402; MANUFACTURER: Vishay Dale
R97 R656 R742 = 1R_ZeroOhmResistor1_16W0603: Resistor Zero ohm Jumper 0603; MANUFACTURER: PANASONIC
R680 = 1R_10KOhmResistor1_10W1%0402: Resistor 10Kohm 1/10W 1% 0402; MANUFACTURER: Panasonic-ECG
R681 = 1R_19.6KohmResistor1_16W1%0402: Resistor 19.6Kohm 1/16W 1% 0402; MANUFACTURER: STACKPOLE ELECTRONICS
U62 = TPS63010YFFR: MANUFACTURER: TI
U79 = TPS61085DGKT: MANUFACTURER: TI
U86 = LP38693MP-ADJ_NOPB: MANUFACTURER: TI
R754 R755 = 1R_240OhmResistor1_16W0402: Resistor 240 ohm 1/16W 1% 0402; MANUFACTURER: STACKPOLE ELECTRONICS
U90 U91 = MT41K256M16TW-107_AIT_P
C106 = 04025C472KAT2A
J3 = 2J_ConnectorRJ45_10_0: Connector MagRJ-45 Jack w/LED 10_100Mb - Auto MDIX; MANUFACTURER: Link
R76 R104 R108-R111 = 1R_2.2KOhmResistor1_16W0402: MANUFACTURER: VishayDale
R99-R102 = 1R_49.9OhmResistor1_16W0402: Resistor 49.9ohm 1/16W 1% 0402; MANUFACTURER: PANASONIC
R103 = 1R_4.87Kohm1_16W1%smd0402: Resistor 4.87Kohm 1/16W 1% 0402; MANUFACTURER: STACKPOLE ELECTRONICS
U9 = TLK105LRHBR: MANUFACTURER: TEXAS INSTRUMENTS
U68 U85 = SN74LVC1G08DCKR: MANUFACTURER: TI
U1 = AM5729BABCXEA
FB13 = 1L_FerBead_0: Ferrite Bead 150 Ohm 800mA; MANUFACTURER: Laird-Signal Integrity Products
J22 = 2C_PCIEConnector_10018783: PCIE Connector Card Edge Type 36pin; MANUFACTURER: FCI
L3 = 1L_NFM21PC474_EMIFilter_0: EMI/RF Suppression Filter; MANUFACTURER: Murata
M1 = 2H_Shunt0.1in: Shunt 0.1in pitch; MANUFACTURER: TE Connectivity
R580 R581 R650 R655 = 1R_100ohm1_16W1%SMD0402: Resistor 100ohm 1/10W 1% 0402; Cost100: 0.02; MANUFACTURER: PANASONIC; MfrNum: ERJ-2RKF1000X; PartName: 100ohm1/10W1%0402; TIIntPartnumber: 1R0246
U44 = SN74LVC1G125DCKR: IC, BUS BUFFER, TRI-ST, N-INV, SC70-5; MANUFACTURER: TI
U45 = CDCM9102RHBT: MANUFACTURER: TI
Y7 = 1Y_Oscillator25MHzSMD: Oscillator 25MHz 50ppm SMD 3.3V; MANUFACTURER: Abracon

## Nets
AGNDFRAME_PRU1ETH0: C106.2 J3.SHLD1 J3.SHLD2
DGND: C6.2 C7.2 C8.2 C9.2 C10.2 C11.2 C12.2 C13.2 C14.2 C15.2 C16.2 C17.2 C20.2 C21.2 C22.2 C23.2 C24.2(NEG) C25.1 C26.1 C27.1 C102.2 C103.2 C104.2 C105.2 C106.1 C107.2 C108.2 C109.2 C110.2 C111.2 C112.2 C113.2 C114.2 C115.2 C268.2 C269.2 C270.2 C271.2 C272.2 C273.2 C274.2 C275.2 C276.2 C277.2 C278.2 C279.2 C280.2 C281.2 C282.2 C283.2 C284.2 C285.2 C286.2 C287.2 C288.2 C289.2 C290.2 C291.2 C292.2 C293.2 C294.2 C295.2 C296.2 C297.2 C298.2 C299.2 C300.2 C301.2 C302.2 C303.2 C304.2 C305.2 C306.2 C307.2 C308.2 C309.2 C310.2 C317.2 C318.2 C320.2 C321.2 C322.2 C324.2 C326.2 C382.2 C383.2 C392.2 C399.2 C400.2 C401.2 C402.2 C403.2 C404.2 C405.2 C406.2 C411.2(NEG) C412.2(NEG) C415.2 C416.2 C417.2 C418.2 C419.2 C440.2(NEG) C441.2(NEG) C450.2 C451.2 C452.2 C453.2 C458.2 C459.2 C460.2 C461.2 C462.2 C463.2 C464.2 C465.2 C466.1 C467.1 C468.2 C469.2 C470.2 C471.2 C472.2 C476.2 C488.2 C489.2 C490.2 C491.2 C492.2 C493.2 C494.2 C495.2 C496.2 C497.2 C498.2 C499.2 C500.2 C501.2 C502.2 C504.2 C505.2 C506.2 C507.2 C508.2 C509.2 C510.2 C511.2 C512.2 C513.2 C514.2 C515.2 C516.2 C517.2 C518.2 C519.2 C520.2 C522.2 C523.2 C524.2 C548.2 C550.2 C551.2 C552.2 C553.2 C556.2 C562.2 C578.2 D2.2 J1.2 J1.3 J2.2 J3.8 J22.A4 J22.A12 J22.A15 J22.A18 J22.B4 J22.B7 J22.B13 J22.B16 J22.B17 J22.B18 J46.1 L3.2(GND) R16.2(P2) R89.2(P2) R103.1(P1) R104.1(P1) R108.1(P1) R109.1(P1) R110.1(P1) R111.1(P1) R425.2 R427.1(P1) R430.2 R431.2 R432.2 R539.1 R542.1 R547.2(P2) R550.2(P2) R570.2 R571.2 R648.1(P1) R680.1 R754.1(P1) R755.1(P1) R798.1 R810.2 R934.2(P2) R955.1 SCKT1.MCH2 SCKT1.MCH4 SW3.1 SW3.2 TP8.1 TP9.1 TP10.1 TP11.1 U1.A1(VSS) U1.A2(VSS) U1.A6(VSS) U1.A14(VSS) U1.A23(VSS) U1.A28(VSS) U1.AA8(VSS) U1.AA9(VSS) U1.AA10(VSS) U1.AA11(VSSA_USB) U1.AA14(VSS) U1.AA15(VSS) U1.AA20(VSS) U1.AB11(VSSA_USB) U1.AB14(VSS) U1.AB20(VSS) U1.AD1(VSS) U1.AD10(VSSA_USB3) U1.AD13(VSSA_PCIE) U1.AD19(VSSA_HDMI) U1.AD24(VSS) U1.AE10(VSSA_SATA) U1.AE13(VSSA_PCIE) U1.AE19(VSSA_HDMI) U1.AG1(VSS) U1.AH1(VSS) U1.AH2(VSS) U1.AH8(VSS) U1.AH20(VSS) U1.AH28(VSS) U1.B1(VSS) U1.D13(VSS) U1.D19(VSS) U1.E13(VSS) U1.E19(VSS) U1.F1(VSS) U1.F7(VSS) U1.G7(VSS) U1.G8(VSS) U1.G9(VSS) U1.H12(VSS) U1.J12(VSS) U1.J15(VSS) U1.J28(VSS) U1.K1(VSS) U1.K4(VSS) U1.K5(VSS) U1.K15(VSS) U1.K24(VSS) U1.K25(VSS) U1.L13(VSS) U1.L14(VSS) U1.M19(VSS) U1.N14(VSS) U1.N15(VSS) U1.N19(VSS) U1.N24(VSS) U1.N25(VSS) U1.P28(VSS) U1.R1(VSS) U1.R12(VSS) U1.R13(VSS) U1.R15(VSS) U1.R21(VSS) U1.T10(VSS) U1.T11(VSS) U1.T12(VSS) U1.T14(VSS) U1.T15(VSS) U1.T17(VSS) U1.T18(VSS) U1.T21(VSS) U1.U14(VSSA_VIDEO) U1.U15(VSS) U1.U17(VSS) U1.U20(VSS) U1.U21(VSS) U1.V15(VSS) U1.V17(VSS) U1.W1(VSS) U1.W15(VSS) U1.W24(VSS) U1.W25(VSS) U1.W28(VSS) U3.A1(PKG_GND) U3.A4(REFGND1) U3.A7(GNDANA) U3.A13(PKG_GND) U3.B2(GPADC_IN0) U3.B8(SYNCDCDC) U3.B10(PKG_GND) U3.B11(PKG_GND) U3.C2(GPADC_IN1) U3.C3(GPADC_IN2) U3.C12(SMPS12_FBK_GND) U3.D4(SMPS7_GND) U3.D5(SMPS7_GND) U3.D6(PKG_GND) U3.D7(PKG_GND) U3.D10(SMPS1_GND) U3.E4(SMPS7_GND) U3.E7(GNDANA) U3.E8(PKG_GND) U3.E9(SMPS1_GND) U3.E10(SMPS1_GND) U3.F4(SMPS4_GND) U3.F5(GNDANA) U3.F6(PKG_GND) U3.F7(PKG_GND) U3.F9(SMPS2_GND) U3.F10(SMPS2_GND) U3.G4(SMPS4_GND) U3.G5(SMPS4_GND) U3.G7(PKG_GND) U3.G10(SMPS2_GND) U3.H4(SMPS5_GND) U3.H5(SMPS5_GND) U3.H6(PKG_GND) U3.H7(PKG_GND) U3.H10(SMPS3_GND) U3.J4(SMPS5_GND) U3.J6(PKG_GND) U3.J9(SMPS3_GND) U3.J10(SMPS3_GND) U3.K3(SMPS45_FDBK_GND) U3.L5(SMPS6_GND) U3.L6(SMPS6_GND) U3.L7(SMPS9_GND) U3.L8(SMPS9_GND) U3.L9(SMPS8_GND) U3.L10(SMPS8_GND) U3.M1(PKG_GND) U3.M2(PKG_GND) U3.M12(GNDDIG) U3.M13(GNDANA) U3.N1(PKG_GND) U3.N2(VIO_GND) U3.N13(PKG_GND) U9.TPAD U44.3(GND) U45.14(GND) U45.22(GND) U45.TPAD(PWRPAD) U50.2 U62.B4(SYNC) U62.C1(PGND) U62.C2(PGND) U62.C3(GND) U62.D3(GND) U62.E4(GND) U68.3(GND) U79.4(GND) U85.3(GND) U86.5(GND) U90.A9(VSS1) U90.B1(VSSQ) U90.B3(VSS2) U90.B9(VSSQ) U90.D1(VSSQ) U90.D8(VSSQ) U90.E1(VSS3) U90.E2(VSSQ) U90.E8(VSSQ) U90.F9(VSSQ) U90.G1(VSSQ) U90.G8(VSS4) U90.G9(VSSQ) U90.J2(VSS5) U90.J8(VSS6) U90.M1(VSS7) U90.M9(VSS8) U90.P1(VSS9) U90.P9(VSS10) U90.T1(VSS11) U90.T9(VSS12) U91.A9(VSS1) U91.B1(VSSQ) U91.B3(VSS2) U91.B9(VSSQ) U91.D1(VSSQ) U91.D8(VSSQ) U91.E1(VSS3) U91.E2(VSSQ) U91.E8(VSSQ) U91.F9(VSSQ) U91.G1(VSSQ) U91.G8(VSS4) U91.G9(VSSQ) U91.J2(VSS5) U91.J8(VSS6) U91.M1(VSS7) U91.M9(VSS8) U91.P1(VSS9) U91.P9(VSS10) U91.T1(VSS11) U91.T9(VSS12) U96.3(GND) Y7.2(GND) ; also on sheet 1 2 3 4 5 6 8 9 11 12 13 14 15 16 17 18 25 26 27 28 29 30 31 32 33 34 35
V1_8D: C405.1 C406.1 D24.3(Anode) D25.3(Anode) Q26.3(COLLECTOR) Q27.3(COLLECTOR) R658.1(P1) R897.1 R901.1 R933.1(P1) U1.AA7(VDDS_MLBP) U1.AA18(VDDS18V_DDR1) U1.AA19(VDDS18V_DDR1) U1.G18(VDDS18V) U1.H17(VDDS18V) U1.J21(VDDS18V_DDR2) U1.J22(VDDS18V_DDR2) U1.M8(VDDS18V) U1.M9(VDDS18V) U1.N8(VDDS18V) U1.N21(VDDS18V_DDR2) U1.P8(VDDS18V) U1.P20(VDDS18V_DDR2) U1.P21(VDDS18V_DDR2) U1.R8(VDDS18V) U1.T8(VDDS18V) U1.V21(VDDS18V) U1.V22(VDDS18V) U1.W17(VDDS18V) U1.W18(VDDS18V) U1.W21(VDDS18V_DDR1) U1.Y7(VDDS_MLBP) U1.Y21(VDDS18V_DDR1) ; also on sheet 5 25 28 29 33
V1_8PHY_HDMI: U1.Y17(VDDA_HDMI) ; also on sheet 33
V1_8PHY_LDO3: C392.1 U3.K11(LDO3_OUT) ; also on sheet 33
V1_8PHY_LDO4: R854.1(P1) ; also on sheet 33
V1_8PHY_PCIE: U1.AA16(VDDA_PCIE1) U1.AA17(VDDA_PCIE0) U1.W14(VDDA_PCIE) ; also on sheet 33
V1_8PHY_SATA: U1.V13(VDDA_SATA) ; also on sheet 33
V1_8PHY_USB: U1.AA13(VDDA_USB1) U1.AB12(VDDA_USB2) U1.W12(VDDA_USB3) ; also on sheet 33
V1_8PLL: C382.1 U1.AD16(VDDA_OSC) U1.AE16(VDDA_OSC) U3.B5(LDOLN_OUT) ; also on sheet 33
V1_8PLLA: U1.M14(VDDA_ABE_PER) U1.N16(VDDA_MPU) U1.R14(VDDA_GPU) U1.R17(VDDA_IVA) ; also on sheet 33
V1_8PLLB: U1.N11(VDDA_DEBUG) U1.N12(VDDA_DSP_EVE) U1.P14(VDDA_VIDEO) U1.P15(VDDA_GMAC_CORE) U1.P16(VDDA_DDR) ; also on sheet 33
V3_3ACDCM: C320.1 C321.1 C322.1 C324.1 L3.3(OUT) U45.1(VDD2_OUT1) U45.4(VDD1_OUT0)
V3_3APCIE: C307.1 C308.1 C309.1 C310.1 C326.1 FB13.1 R546.2 R548.2 R549.2 U45.9(VDD) U45.16(VDD) U45.18(VDD) U45.20(VDD) Y7.4(VCC)
V3_3AUX_PCIE: C556.1 J22.B10 J49.2 R654.2
V3_3D: C104.1 C105.1 C107.1 C113.1 C450.1 C451.1 C469.1 C470.1 FB13.2 J22.A9 J22.A10 J22.B8 J46.3 J49.1 L3.1(IN) Q26.2(EMMITTER) R18.2 R76.2(P2) R77.2(P2) R78.2(P2) R97.1(P1) R99.1(P1) R100.1(P1) R101.1(P1) R102.1(P1) R107.2 R419.2(P2) R543.1 R544.1 R545.2 R649.2 R678.2(P2) R679.2(P2) R742.1(P1) R811.1 R814.1 R894.2 R896.2 R954.1 U1.AB6(VDDSHV7) U1.AB7(VDDSHV7) U1.AD5(VDDSHV6) U1.AD7(VDDSHV6) U1.AE7(VDDSHV6) U1.AF5(VDDSHV6) U1.B6(VDDSHV2) U1.B23(VDDSHV3) U1.C24(VDDSHV4) U1.D10(VDDSHV2) U1.D16(VDDSHV3) U1.D22(VDDSHV3) U1.E3(VDDSHV1) U1.E5(VDDSHV1) U1.E10(VDDSHV2) U1.E16(VDDSHV3) U1.E22(VDDSHV3) U1.G4(VDDSHV1) U1.G5(VDDSHV1) U1.G15(VDDSHV3) U1.H8(VDDSHV1) U1.H9(VDDSHV1) U1.H10(VDDSHV2) U1.H11(VDDSHV2) U1.H15(VDDSHV3) U1.H16(VDDSHV3) U1.H18(VDDSHV3) U1.H19(VDDSHV3) U1.J8(VDDSHV11) U1.K8(VDDSHV11) U1.N4(VDDSHV10) U1.N5(VDDSHV10) U1.P10(VDDSHV10) U1.R7(VDDSHV10) U1.R10(VDDSHV10) U1.T4(VDDSHV10) U1.T5(VDDSHV10) U1.U10(VDDSHV9) U1.V12(VDDSHV5) U1.W4(VDDSHV9) U1.W5(VDDSHV9) U3.D9(VIO_IN) U3.J8(SMPS9_FBK) U9.21(VDD33_IO) U44.5(VCC) U68.5(VCC) U85.5(VCC) ; also on sheet 2 3 4 5 6 8 9 11 12 13 14 15 16 17 18 25 26 27 28 29 30 31 32 33 34 35
V3_3D_PRU1ETH0JCK: C102.1 C103.1 J3.3 J3.4 R77.1(P1)
V3_3USB: C399.1 C400.1 C401.1 U1.AA12(VDDA33V_USB1) U1.Y12(VDDA33V_USB2) U3.B9(LDOUSB_OUT)
V3_7LCD: C472.1 R681.1 U86.3(VOUT) ; also on sheet 5
V5_0D: C418.1 C419.1 C476.1 R424.2(P2) U62.E1(VOUT) U62.E2(VOUT) ; also on sheet 4 14 16 18 34
V5_0D_EN: R419.1(P1) U62.A4(EN)
V5_0DFB: R424.1(P1) R427.2(P2) U62.E3(FB)
V12_0D: C303.1 C304.1 C461.1 C462.1 D20.1(CATHODE) J22.A2 J22.A3 J22.B1 J22.B2 J22.B3 R647.2 ; also on sheet 18
VDD_CORE: R640.2(I2) R931.1(P1) U1.H13(VDD) U1.H14(VDD) U1.J17(VDD) U1.J18(VDD) U1.L7(VDD) U1.L8(VDD) U1.N10(VDD) U1.N13(VDD) U1.P11(VDD) U1.P12(VDD) U1.P13(VDD) U1.R11(VDD) U1.R16(VDD) U1.R19(VDD) U1.T13(VDD) U1.T16(VDD) U1.T19(VDD) U1.U8(VDD) U1.U9(VDD) U1.U13(VDD) U1.U16(VDD) U1.V8(VDD) U1.V16(VDD) U3.B1(SMPS7_FDBK) ; also on sheet 33
VDD_DSPEVE: R642.2(I2) U1.J13(VDD_DSPEVE) U1.K10(VDD_DSPEVE) U1.K11(VDD_DSPEVE) U1.K12(VDD_DSPEVE) U1.K13(VDD_DSPEVE) U1.L10(VDD_DSPEVE) U1.L11(VDD_DSPEVE) U1.L12(VDD_DSPEVE) U1.M10(VDD_DSPEVE) U1.M11(VDD_DSPEVE) U1.M12(VDD_DSPEVE) U1.M13(VDD_DSPEVE) U3.K2(SMPS45_FDBK) ; also on sheet 33
VDD_GPU: C268.1 L17.2 U1.U11(VDD_GPU) U1.U12(VDD_GPU) U1.V10(VDD_GPU) U1.V11(VDD_GPU) U1.V14(VDD_GPU) U1.W10(VDD_GPU) U1.W11(VDD_GPU) U1.W13(VDD_GPU) U3.K6(SMPS6_FBK) ; also on sheet 33
VDD_IVA: C270.1 L19.2 U1.U18(VDD_IVA) U1.U19(VDD_IVA) U1.V18(VDD_IVA) U1.V19(VDD_IVA) U3.L11(SMPS8_FDBK) ; also on sheet 33
VDD_MPU: R641.2(I2) U1.K17(VDD_MPU) U1.K18(VDD_MPU) U1.L15(VDD_MPU) U1.L16(VDD_MPU) U1.L17(VDD_MPU) U1.L18(VDD_MPU) U1.L19(VDD_MPU) U1.M15(VDD_MPU) U1.M16(VDD_MPU) U1.M17(VDD_MPU) U1.M18(VDD_MPU) U1.N17(VDD_MPU) U1.N18(VDD_MPU) U1.P17(VDD_MPU) U1.P18(VDD_MPU) U1.R18(VDD_MPU) U3.B13(SMPS12_FBK) ; also on sheet 33
VDD_RTC: C402.1 R930.1(P1) U3.A5(LDO9_OUT)
VDDR2_VREF: C503.2 C504.1 C505.1 C521.2 C522.1 C523.1 C524.1 U1.N22(DDR2_VREF) U90.H1(VREFDQ) U90.M8(VREFCA) U91.H1(VREFDQ) U91.M8(VREFCA) ; also on sheet 9
VDDS_DDR: C488.1 C489.1 C490.1 C491.1 C492.1 C493.1 C494.1 C495.1 C496.1 C497.1 C498.1 C499.1 C500.1 C501.1 C502.1 C503.1 C506.1 C507.1 C508.1 C509.1 C510.1 C511.1 C512.1 C513.1 C514.1 C515.1 C516.1 C517.1 C518.1 C519.1 C520.1 C521.1 R639.1(I1) R656.1(P1) R801.1(I1) U3.K13(SMPS3_FDBK) U90.A1(VDDQ) U90.A8(VDDQ) U90.B2(VDD) U90.C1(VDDQ) U90.C9(VDDQ) U90.D2(VDDQ) U90.D9(VDD) U90.E9(VDDQ) U90.F1(VDDQ) U90.G7(VDD) U90.H2(VDDQ) U90.H9(VDDQ) U90.K2(VDD) U90.K8(VDD) U90.N1(VDD) U90.N9(VDD) U90.R1(VDD) U90.R9(VDD) U91.A1(VDDQ) U91.A8(VDDQ) U91.B2(VDD) U91.C1(VDDQ) U91.C9(VDDQ) U91.D2(VDDQ) U91.D9(VDD) U91.E9(VDDQ) U91.F1(VDDQ) U91.G7(VDD) U91.H2(VDDQ) U91.H9(VDDQ) U91.K2(VDD) U91.K8(VDD) U91.N1(VDD) U91.N9(VDD) U91.R1(VDD) U91.R9(VDD) ; also on sheet 1 9
AM57XX_PCIE_PERn0: J22.A17 U1.AG13(PCIE_RXN0)
AM57XX_PCIE_PERp0: J22.A16 U1.AH13(PCIE_RXP0)
AM57XX_PCIE_PETn0: C477.1 U1.AG14(PCIE_TXN0)
AM57XX_PCIE_PETp0: C478.1 U1.AH14(PCIE_TXP0)
AM57XX_PCIE_REF_CLKN: C438.2 R581.1(P1) U1.AH15(LJCB_CLKN)
AM57XX_PCIE_REF_CLKP: C439.2 R581.2(P2) U1.AG15(LJCB_CLKP)
AM57XX_PRU1ETH0_MRCLK: R83.2(P2) U1.Y1(UART3_TXD/PR1_MII0_MR0CLK)
AM57XX_PRU1ETH0_RXDV: R86.2(P2) U1.V2(UART3_RXD/PR1_MII0_RXDV)
AM57XX_PRU1ETH_MDCLK: R96.2(P2) ; also on sheet 17 34
AM57XX_PRU1ETH_MDDATA: R98.2(P2) ; also on sheet 17
AM57XX_RGMII0_RD0: R81.2(P2) ; also on sheet 28
AM57XX_RGMII0_RD1: R84.2(P2) ; also on sheet 28
AM57XX_RGMII0_RD2: R80.2(P2) ; also on sheet 28
AM57XX_RGMII0_RD3: R85.2(P2) ; also on sheet 28
AM57XX_RGMII0_RXCLK: R79.2(P2) ; also on sheet 28
AM57XX_RGMII0_RXCTL: R82.2(P2) ; also on sheet 28
AM57XX_RGMII0_TD0: R88.2(P2) ; also on sheet 28
AM57XX_RGMII0_TD1: R90.2(P2) ; also on sheet 28
AM57XX_RGMII0_TD2: R87.2(P2) ; also on sheet 28
AM57XX_RGMII0_TD3: R94.2(P2) ; also on sheet 28
AM57XX_RGMII0_TXCLK: R92.2(P2) ; also on sheet 28
AM57XX_RGMII0_TXCTL: R91.2(P2) ; also on sheet 28
DDR2_A0: U1.R25(DDR2_A0) U90.N3(A0) U91.N3(A0) ; also on sheet 9
DDR2_A1: U1.R26(DDR2_A1) U90.P7(A1) U91.P7(A1) ; also on sheet 9
DDR2_A2: U1.R28(DDR2_A2) U90.P3(A2) U91.P3(A2) ; also on sheet 9
DDR2_A3: U1.R27(DDR2_A3) U90.N2(A3) U91.N2(A3) ; also on sheet 9
DDR2_A4: U1.P23(DDR2_A4) U90.P8(A4) U91.P8(A4) ; also on sheet 9
DDR2_A5: U1.P22(DDR2_A5) U90.P2(A5) U91.P2(A5) ; also on sheet 9
DDR2_A6: U1.P25(DDR2_A6) U90.R8(A6) U91.R8(A6) ; also on sheet 9
DDR2_A7: U1.N20(DDR2_A7) U90.R2(A7) U91.R2(A7) ; also on sheet 9
DDR2_A8: U1.P27(DDR2_A8) U90.T8(A8) U91.T8(A8) ; also on sheet 9
DDR2_A9: U1.N27(DDR2_A9) U90.R3(A9) U91.R3(A9) ; also on sheet 9
DDR2_A10: U1.N23(DDR2_A10) U90.L7(A10_AP) U91.L7(A10_AP) ; also on sheet 9
DDR2_A11: U1.P26(DDR2_A11) U90.R7(A11) U91.R7(A11) ; also on sheet 9
DDR2_A12: U1.N28(DDR2_A12) U90.N7(A12~{/BC}) U91.N7(A12~{/BC}) ; also on sheet 9
DDR2_A13: U1.T22(DDR2_A13) U90.T3(A13) U91.T3(A13) ; also on sheet 9
DDR2_A14: U1.R22(DDR2_A14) U90.T7(A14) U91.T7(A14) ; also on sheet 9
DDR2_A15: U1.U22(DDR2_A15) U90.M7(NC5) U91.M7(NC5) ; also on sheet 9
DDR2_BA0: U1.U23(DDR2_BA0) U90.M2(BA0) U91.M2(BA0) ; also on sheet 9
DDR2_BA1: U1.U27(DDR2_BA1) U90.N8(BA1) U91.N8(BA1) ; also on sheet 9
DDR2_BA2: U1.U26(DDR2_BA2) U90.M3(BA2) U91.M3(BA2) ; also on sheet 9
DDR2_CASn: U1.U28(DDR2_CASn) U90.K3(\\~{CAS}) U91.K3(\\~{CAS}) ; also on sheet 9
DDR2_CKE: U1.U24(DDR2_CKE) U90.K9(CKE) U91.K9(CKE) ; also on sheet 9
DDR2_CLK: U1.T28(DDR2_CK) U90.J7(CK) U91.J7(CK) ; also on sheet 9
DDR2_CLKn: U1.T27(DDR2_CKn) U90.K7(\\~{CK}) U91.K7(\\~{CK}) ; also on sheet 9
DDR2_CS0n: U1.P24(DDR2_CSN0) U90.L2(\\~{CS}) U91.L2(\\~{CS}) ; also on sheet 9
DDR2_D0: U1.E26(DDR2_D0) U90.E3(DQ0)
DDR2_D1: U1.G25(DDR2_D1) U90.F2(DQ2)
DDR2_D2: U1.F25(DDR2_D2) U90.G2(DQ6)
DDR2_D3: U1.F24(DDR2_D3) U90.H3(DQ4)
DDR2_D4: U1.F26(DDR2_D4) U90.F7(DQ1)
DDR2_D5: U1.F27(DDR2_D5) U90.H8(DQ5)
DDR2_D6: U1.E27(DDR2_D6) U90.F8(DQ3)
DDR2_D7: U1.E28(DDR2_D7) U90.H7(DQ7)
DDR2_D8: U1.H23(DDR2_D8) U90.D7(DQ8)
DDR2_D9: U1.H25(DDR2_D9) U90.A2(DQ13)
DDR2_D10: U1.H24(DDR2_D10) U90.C3(DQ9)
DDR2_D11: U1.H26(DDR2_D11) U90.A3(DQ15)
DDR2_D12: U1.G26(DDR2_D12) U90.C2(DQ11)
DDR2_D13: U1.J25(DDR2_D13) U90.B8(DQ14)
DDR2_D14: U1.J26(DDR2_D14) U90.A7(DQ12)
DDR2_D15: U1.J24(DDR2_D15) U90.C8(DQ10)
DDR2_D16: U1.L22(DDR2_D16) U91.E3(DQ0)
DDR2_D17: U1.K20(DDR2_D17) U91.H8(DQ5)
DDR2_D18: U1.K21(DDR2_D18) U91.H3(DQ4)
DDR2_D19: U1.L23(DDR2_D19) U91.F7(DQ1)
DDR2_D20: U1.L24(DDR2_D20) U91.F8(DQ3)
DDR2_D21: U1.J23(DDR2_D21) U91.F2(DQ2)
DDR2_D22: U1.K22(DDR2_D22) U91.G2(DQ6)
DDR2_D23: U1.J20(DDR2_D23) U91.H7(DQ7)
DDR2_D24: U1.L27(DDR2_D24) U91.D7(DQ8)
DDR2_D25: U1.L26(DDR2_D25) U91.A3(DQ15)
DDR2_D26: U1.L25(DDR2_D26) U91.C2(DQ11)
DDR2_D27: U1.L28(DDR2_D27) U91.A7(DQ12)
DDR2_D28: U1.M23(DDR2_D28) U91.C8(DQ10)
DDR2_D29: U1.M24(DDR2_D29) U91.A2(DQ13)
DDR2_D30: U1.M25(DDR2_D30) U91.C3(DQ9)
DDR2_D31: U1.M26(DDR2_D31) U91.B8(DQ14)
DDR2_DQM0: U1.F28(DDR2_DQM0) U90.E7(LDM)
DDR2_DQM1: U1.G24(DDR2_DQM1) U90.D3(UDM)
DDR2_DQM2: U1.K23(DDR2_DQM2) U91.E7(LDM)
DDR2_DQM3: U1.M22(DDR2_DQM3) U91.D3(UDM)
DDR2_DQS0: U1.G28(DDR2_DQS0) U90.F3(LDQS)
DDR2_DQS1: U1.H27(DDR2_DQS1) U90.C7(UDQS)
DDR2_DQS2: U1.K27(DDR2_DQS2) U91.F3(LDQS)
DDR2_DQS3: U1.M28(DDR2_DQS3) U91.C7(UDQS)
DDR2_DQSn0: U1.G27(DDR2_DQS0n) U90.G3(\\~{LDQS})
DDR2_DQSn1: U1.H28(DDR2_DQS1n) U90.B7(\\~{UDQS})
DDR2_DQSn2: U1.K28(DDR2_DQS2n) U91.G3(\\~{LDQS})
DDR2_DQSn3: U1.M27(DDR2_DQS3n) U91.B7(\\~{UDQS})
DDR2_ODT: U1.R23(DDR2_ODT0) U90.K1(ODT) U91.K1(ODT) ; also on sheet 9
DDR2_RASn: U1.T23(DDR2_RASn) U90.J3(\\~{RAS}) U91.J3(\\~{RAS}) ; also on sheet 9
DDR2_RESETn: U1.R24(DDR2_RST) U90.T2(\\~{RESET}) U91.T2(\\~{RESET}) ; also on sheet 9
DDR2_WEn: U1.U25(DDR2_WEn) U90.L3(\\~{WE}) U91.L3(\\~{WE}) ; also on sheet 9
ETH_MDIO_CLK: R95.2(P2) ; also on sheet 25 28
ETH_MDIO_DATA: R105.2(P2) ; also on sheet 25 28
GPIO_PCIE_RSTDRVn: R955.2 U44.1(~{OE}) ; also on sheet 34
GPIO_PCIE_SWRSTn: R954.2 U85.2(B) ; also on sheet 34
GPIO_PRU1_ETH0_RESETn: R112.2(P2) ; also on sheet 34
GPIO_USB2_VBUS_DET: R811.2 U96.4(Y) ; also on sheet 34
GPIO_VPP_PWR_EN: R638.2(P2) ; also on sheet 34
IND_I2C_SCL: R14.2(P2) R652.2(P2) ; also on sheet 5 13 15 18 28 34
IND_I2C_SDA: R15.2(P2) R653.2(P2) ; also on sheet 5 13 15 18 28 34
PCI_CONN_REFN: C436.1 U45.5(OUT0N)
PCI_CONN_REFP: C437.1 U45.6(OUT0P)
PCIE_CRDPRESENT: R650.1(P1) ; also on sheet 34
PCIE_PERSTn: J22.A11 R545.1 U44.4(Y)
PCIE_REFCLKN: C436.2 J22.A14 R580.2(P2)
PCIE_REFCLKP: C437.2 J22.A13 R580.1(P1)
PCIE_RESETn: R568.2(P2) U85.1(A) ; also on sheet 31
PCIE_SMB_CLK: J22.B5 R652.1(P1)
PCIE_SMB_DATA: J22.B6 R653.1(P1)
PCIE_TCK: J22.A5 R542.2
PCIE_TDI: J22.A6 R543.2
PCIE_TDO: J22.A7 TP20.1
PCIE_TMS: J22.A8 R544.2
PCIE_TRSTn: J22.B9 R539.2
PCIE_WAKEn: R655.1(P1) ; also on sheet 34
PCIECONN_PETn0: C477.2 J22.B15
PCIECONN_PETp0: C478.2 J22.B14
PHY_RESETn: U68.2(B) ; also on sheet 17 25 26 27 28 31
PMIC_EN: U3.E5(nSLEEP) ; also on sheet 29
PMIC_INT: U3.K1(INT) ; also on sheet 34
PMIC_RESET_IN: R794.1(P1) U3.K9(RESET_IN) ; also on sheet 11
PMIC_RESET_OUTn: R814.2 U3.G6(RESET_OUT) ; also on sheet 31
PRU1ETH0_25MHzCLK: U9.23(XI) ; also on sheet 28
PRU1ETH0_COL: R95.1(P1) R104.2(P2) R105.1(P1) R106.2(P2) U9.29(COL)
PRU1ETH0_CRS: R94.1(P1) U9.27(CRS)
PRU1ETH0_INTn: U9.8(PWRDNn/INTn) ; also on sheet 34
PRU1ETH0_LINKLED: R76.1(P1) R93.2(P2) U9.17(LED_LINK)
PRU1ETH0_MDC: R96.1(P1) U9.20(MDC)
PRU1ETH0_MDIO: R98.1(P1) U9.19(MDIO)
PRU1ETH0_RESETn: U9.18(RESET_N) U68.4(Y)
PRU1ETH0_RXCLK: R83.1(P1) U9.25(RX_CLK)
PRU1ETH0_RXD0: R88.1(P1) R111.2(P2) U9.30(RXD_0)
PRU1ETH0_RXD1: R90.1(P1) R110.2(P2) U9.31(RXD_1)
PRU1ETH0_RXD2: R91.1(P1) R109.2(P2) U9.32(RXD_2)
PRU1ETH0_RXD3: R92.1(P1) R108.2(P2) U9.1(RXD_3)
PRU1ETH0_RXDV: R86.1(P1) U9.26(RX_DV)
PRU1ETH0_RXERR: R87.1(P1) U9.28(RX_ERR)
PRU1ETH0_TXCLK: R79.1(P1) U9.2(TX_CLK)
PRU1ETH0_TXD0: R81.1(P1) U9.4(TXD_0)
PRU1ETH0_TXD1: R84.1(P1) U9.5(TXD_1)
PRU1ETH0_TXD2: R85.1(P1) U9.6(TXD_2)
PRU1ETH0_TXD3: R82.1(P1) U9.7(TXD_3)
PRU1ETH0_TXEN: R80.1(P1) U9.3(TX_EN)
PRU1ETHER0_RDN: J3.2 R99.2(P2) U9.9(RD-)
PRU1ETHER0_RDP: J3.1 R100.2(P2) U9.10(RD+)
PRU1ETHER0_TDN: J3.6 R101.2(P2) U9.11(TD-)
PRU1ETHER0_TDP: J3.5 R102.2(P2) U9.12(TD+)
RSTOUTTOPMIC: U3.E6(nRESWARM) ; also on sheet 31
SERDES_REF_CLKN: C438.1 U45.2(OUT1N)
SERDES_REF_CLKP: C439.1 U45.3(OUT1P)
VADD33_PRU1ETH0: C112.1 R97.2(P2) U9.14(AVDD33)
VAM574X_DDR1: C6.1 C7.1 C8.1 C9.1 C10.1 C11.1 C12.1 C114.1 C115.1 C441.1(POS) R639.2(I2) U1.AA21(VDDS_DDR1) U1.AA22(VDDS_DDR1) U1.AB21(VDDS_DDR1) U1.AB22(VDDS_DDR1) U1.AB24(VDDS_DDR1) U1.AB25(VDDS_DDR1) U1.AC22(VDDS_DDR1) U1.AD26(VDDS_DDR1) U1.AG20(VDDS_DDR1) U1.AG28(VDDS_DDR1) U1.AH27(VDDS_DDR1) U1.W16(VDDS_DDR1) U1.W27(VDDS_DDR1)
VAM574X_DDR2: C13.1 C14.1 C15.1 C16.1 C17.1 C440.1(POS) C550.1 C551.1 C552.1 C553.1 R801.2(I2) U1.E24(VDDS_DDR2) U1.G22(VDDS_DDR2) U1.G23(VDDS_DDR2) U1.H20(VDDS_DDR2) U1.H21(VDDS_DDR2) U1.H22(VDDS_DDR2) U1.J27(VDDS_DDR2) U1.L20(VDDS_DDR2) U1.L21(VDDS_DDR2) U1.M20(VDDS_DDR2) U1.M21(VDDS_DDR2) U1.T24(VDDS_DDR2) U1.T25(VDDS_DDR2)
VANA_OUT: C302.1 U3.C8(LDOVANA_OUT)
VLDO1_OUT: C383.1 R657.2(P2) U3.C6(LDO1_OUT)
VLDO2_OUT: C318.1 R658.2(P2) U3.B6(LDO2_OUT)
VMAIN: C20.1 C21.1 C22.1 C23.1 C24.1(POS) C272.1 C273.1 C274.1 C275.1 C281.1 C282.1 C283.1 C284.1 C285.1 C317.1 C411.1(POS) C412.1(POS) C415.1 C416.1 C452.1 C453.1 C458.1 C459.1 C464.1 C465.1 C466.2 C467.2 C468.1 C471.1 D2.1 F1.2 L28.1 R19.2(P2) R20.2(P2) TP1.1 U3.A6(LDO12_IN) U3.A9(LDOUSB_IN2) U3.A10(LDO7_LDOUSB_IN) U3.C4(LDO9_IN) U3.C5(LDOLN_IN) U3.C7(VCC1) U3.D11(SMPS1_IN_1) U3.D12(SMPS1_IN_2) U3.D13(SMPS1_IN_3) U3.E1(SMPS7_IN_B1_1) U3.E2(SMPS7_IN_B1_2) U3.E3(SMPS7_IN_B1_3) U3.F1(SMPS4_IN1) U3.F2(SMPS4_IN2) U3.F3(SMPS4_IN3) U3.G11(SMPS2_IN_1) U3.G12(SMPS2_IN_2) U3.G13(SMPS2_IN_3) U3.H11(SMPS3_IN1) U3.H12(SMPS3_IN2) U3.H13(SMPS3_IN3) U3.J1(SMPS5_IN1) U3.J2(SMPS5_IN2) U3.J3(SMPS5_IN3) U3.L12(LDO34_IN) U3.L13(LDO34_IN1) U3.M4(LDO58_IN) U3.M6(SMPS6_IN) U3.M8(SMPS9_IN) U3.M9(SMPS8_IN) U3.N3(LDO6_IN) U3.N4(LDO58_IN) U3.N6(SMPS6_IN) U3.N8(SMPS9_IN) U3.N9(SMPS8_IN) U62.A1(VIN) U62.A2(VIN) U79.6(IN) U79.7(FREQ) U86.4(VIN) U96.5(VCC) ; also on sheet 5 11 13 34
VPP_CONN: J46.2 R797.1(P1)
VPWRIN_JCK: D1.2(ANODE) J1.1 J2.1 ; also on sheet 11
VPWRIN_PREFUSE: D1.1(CATHODE) F1.1
VRTC_OUT: C301.1 R17.2(P2) R794.2(P2) R932.1(P1) R983.2 U3.A8(LDOVRTC_OUT) ; also on sheet 11 29
VSDMMC: Q27.2(EMMITTER) R657.1(P1) R898.2 R900.2 U1.W8(VDDSHV8) U1.Y8(VDDSHV8) ; also on sheet 32 33
VSMPS1_2: C276.1 C277.1 L12.2 L13.2 R641.1(I1)
VSMPS1_SW: L12.1 U3.E11(SMPS1_SW_1) U3.E12(SMPS1_SW_2) U3.E13(SMPS1_SW_3)
VSMPS2_SW: L13.1 U3.F11(SMPS2_SW1) U3.F12(SMPS2_SW2) U3.F13(SMPS2_SW3)
VSMPS3: C278.1 L14.2 R656.2(P2)
VSMPS3_SW: L14.1 U3.J11(SMPS3_SW1) U3.J12(SMPS3_SW2) U3.J13(SMPS3_SW3)
VSMPS4_5: C279.1 C280.1 L15.2 L16.2 R642.1(I1)
VSMPS4_SW: L15.1 U3.G1(SMPS4_SW1) U3.G2(SMPS4_SW2) U3.G3(SMPS4_SW3)
VSMPS5_SW: L16.1 U3.H1(SMPS5_SW1) U3.H2(SMPS5_SW2) U3.H3(SMPS5_SW3)
VSMPS6_SW: L17.1 U3.M5(SMPS6_SW) U3.N5(SMPS6_SW)
VSMPS7: C269.1 L18.2 R640.1(I1)
VSMPS7_SW: L18.1 U3.D1(SMPS7_SW1) U3.D2(SMPS7_SW2) U3.D3(SMPS7_SW3)
VSMPS8_SW: L19.1 U3.M10(SMPS8_SW) U3.N10(SMPS8_SW)
VSMPS9: C271.1 L20.2 R742.2(P2)
VSMPS9_SW: L20.1 U3.M7(SMPS9_SW) U3.N7(SMPS9_SW)
VUSB_VBUS2: R21.2(P2) ; also on sheet 16
N12220066: C108.1 C109.1 C110.1 C111.1 U9.13(PFBIN1) U9.15(PFBOUT) U9.24(PFBIN2)
N16818719: R107.1 R112.1(P1) U68.1(A)
N16819128: R103.2(P2) U9.16(RBIAS)
N17074741: J3.9 R106.1(P1)
N17863265: J3.11 R78.1(P1)
N17863276: J3.12 R93.1(P1)
N18868530: R14.1(P1) R572.2(P2) U3.L1(I2C1_SCL_SCK)
N18868533: R15.1(P1) R588.2(P2) U3.L2(I2C1_SDA_SDI)
N18913166: TP7.1 U3.J5(ENABLE1)
N18913202: R17.1(P1) R934.1(P1) U3.K7(BOOT1)
N18913205: R16.1(P1) U3.L3(BOOT0)
N18913322: R18.1 R983.1 U3.G9(GPIO_7)
N18913403: C26.2 U3.A3(OSC16MIN) Y2.1
N18913412: C25.2 U3.A2(OSC16MOUT) Y2.3
N18913758: C27.2 U3.B7(VBG)
N18914093: C578.1 U3.C1(OSC16MCAP)
N18914190: TP2.1 U3.M11(CLK32KGO)
N18914214: TP3.1 U3.J7(POWERGOOD)
N18914339: SW3.3 SW3.4 U3.G8(PWRON) U50.1
N18914524: TP6.1 U3.C11(RPWRON)
N18915671: R19.1(P1) U3.B3(VCC_SENSE)
N18915723: R20.1(P1) U3.A11(VCC_SENSE2)
N18915943: R21.1(P1) U3.D8(VBUS)
N19258097: R546.1 U45.7(OE)
N19258128: U45.21(XIN) Y7.3(CLK)
N19258198: R547.1(P1) Y7.1(OE)
N19258383: R548.1 U45.11(OS0)
N19258403: R549.1 R550.1(P1) U45.10(OS1)
N19258622: C305.1 U45.17(REG_CAP2)
N19258627: C306.1 U45.19(REG_CAP1)
N19415733: R568.1(P1) U45.12(RSTn)
N19795587: R425.1 U3.B12(GPIO_0)
N19795594: R428.1(P1) U3.C13(GPIO_1)
N19795604: R430.1 U3.A12(GPIO_2)
N19795606: R431.1 U3.H9(GPIO_3)
N19795618: R570.1 U3.C10(GPIO_5)
N19795620: R571.1 U3.N11(GPIO_6)
N19795629: R432.1 U3.K10(GPIO_4)
N19796448: R572.1(P1) U3.M3(I2C2_SCL_SCE)
N19796451: R588.1(P1) U3.H8(I2C2_SDA_SDO)
N19923823: C286.1 U1.J10(CAP_VDDRAM_DSPEVE1)
N19923824: C287.1 U1.J9(CAP_VDDRAM_DSPEVE2)
N19923825: C288.1 U1.J16(CAP_VBBLDO_MPU)
N19923831: C292.1 U1.K19(CAP_VDDRAM_MPU2)
N19923832: C291.1 U1.K16(CAP_VDDRAM_MPU1)
N19923833: C290.1 U1.K9(CAP_VBBLDO_DSPEVE)
N19923834: C289.1 U1.J19(CAP_VDDRAM_CORE2)
N19923844: C293.1 U1.L9(CAP_VDDRAM_CORE1)
N19923845: C294.1 U1.P19(CAP_VDDRAM_CORE4)
N19923846: C295.1 U1.R20(CAP_VBBLDO_IVA)
N19923850: C299.1 U1.Y15(CAP_VDDRAM_CORE3)
N19923851: C298.1 U1.Y14(CAP_VBBLDO_GPU)
N19923852: C297.1 U1.Y13(CAP_VDDRAM_GPU)
N19923853: C296.1 U1.T20(CAP_VDDRAM_IVA)
N19923865: C300.1 U1.Y16(CAP_VDDRAM_CORE5)
N20127658: C403.1 R930.2(P2) R931.2(P2) U1.AB15(VDD_RTC)
N20128389: C404.1 R932.2(P2) R933.2(P2) U1.AB13(VDDA_RTC)
N20190363: C454.2 J40.2 R639.4(SENS2)
N20190375: C454.1 J40.1 R639.3(SENS1)
N20190748: C455.2 J41.1 R640.3(SENS1)
N20190772: C455.1 J41.2 R640.4(SENS2)
N20190931: C456.2 J42.1 R641.3(SENS1)
N20190955: C456.1 J42.2 R641.4(SENS2)
N20191205: C457.2 J43.1 R642.3(SENS1)
N20191229: C457.1 J43.2 R642.4(SENS2)
N20202943: TP21.1 U3.F8(REGEN1)
N20275163: C460.1 U79.8(SS)
N20287248: R647.1 R648.2(P2) U79.2(FB)
N20287275: R646.2 U79.1(COMP)
N20287568: C463.1 R646.1
N20287584: D20.2(ANODE) L28.2 U79.5(SW)
N20301491: J22.A1 R649.1 R650.2(P2)
N20338433: J22.B11 R654.1 R655.2(P2)
N20537306: U44.2(A) U85.4(Y)
N20594970: R678.1(P1) U86.1(VEN)
N20595300: R679.1(P1) U79.3(EN)
N20619479: R680.2 R681.2 U86.2(ADJ)
N20664562: L22.1 U62.B1(L1) U62.B2(L1)
N20664572: C417.1 U62.A3(VINA) U62.B3(VINA1) U62.C4(~{PS}) U62.D4(VSEL)
N20665027: L22.2 U62.D1(L2) U62.D2(L2)
N21519094: R754.2(P2) U90.L8(ZQ)
N21519152: R755.2(P2) U91.L8(ZQ)
N21685968: C548.1 R797.2(P2) U1.K14(RSVK14)
N21685998: J46.4 R638.1(P1) R798.2
N21823186: C549.2 J47.2 R801.4(SENS2)
N21823194: C549.1 J47.1 R801.3(SENS1)
N22373612: R428.2(P2) R810.1 U96.2(A)
N22641301: D24.2(Cathode) Q26.1(BASE) R894.1 R895.1
N22641309: D24.1(REF) R895.2 R896.1 R897.2
N22641383: D25.2(Cathode) Q27.1(BASE) R898.1 R899.1
N22641391: D25.1(REF) R899.2 R900.1 R901.2
N22644059: C562.1 R854.2(P2) U3.K12(LDO4_OUT)
N24756266: J3.10 R89.1(P1)

Not connected (* = marked no-connect by the designer): J3 7*; J22 B12*; SCKT1 MCH1* MCH3*; U1 A27(RSVA27) B28(RSVB28) Y5(RSVY5) Y10(RSVY10); U3 B4(GPADC_REF)* C9(LDO7_OUT)* K4(LDO5_OUT)* K5(LDO8_OUT)* K8(PWRDOWN)* L4(LDO6_OUT)* N12(VPROG/TESTV)*; U9 22(XO)*; U45 8(NC8)* 13(NC13)* 15(NC15)* 23(OSCOUT)* 24(NC24)* 25(NC25)* 26(NC26)* 27(NC27)* 28(NC28)* 29(NC29)* 30(NC30)* 31(NC31)* 32(NC32)*; U90 J1(NC1)* J9(NC2)* L1(NC3)* L9(NC4)*; U91 J1(NC1)* J9(NC2)* L1(NC3)* L9(NC4)*; U96 1(NC)*; Y2 2(NC0)* 4(NC1)*

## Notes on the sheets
sheet 19
- Main 5VDC Power Input
- 4A maximum input current
- Sufficient capacitance needed to
  hold up VMAIN (over 2.7V) for at
  least 1ms after power supply
  shut off. AM57xx device will be
  in POR reset. This will allow
  the PMIC to properly execute its
  power-down sequence.
- Clamp circuits added to guarantee the 3.3V
  supplies V3_3D and VSDMMC never become
  more than 2V above V1_8D during start-up
  or shut-down.
- Circuit needed to detect VPWRIN
  collapse which can initiate a PMIC
  power shut-down sequence such as a
  TPS3808.  Please refer to the
  AM571x IDK EVM for an example.  The
  circuit must drive the PMIC
  RESET_IN low to initiate this
  shut-down sequence.
- It has been later determined that the clamp
  circuit on VSDMMC is not sufficient and the
  PMIC was enhanced to better control
  shut-down sequencing.  Therefore, the
  VDSMMC clamp is no longer required. The
  power-down sequence defined in the Data
  Manual must be met.
- Power On
  Switch
sheet 24
- Note: MDIO Address = 0x00
